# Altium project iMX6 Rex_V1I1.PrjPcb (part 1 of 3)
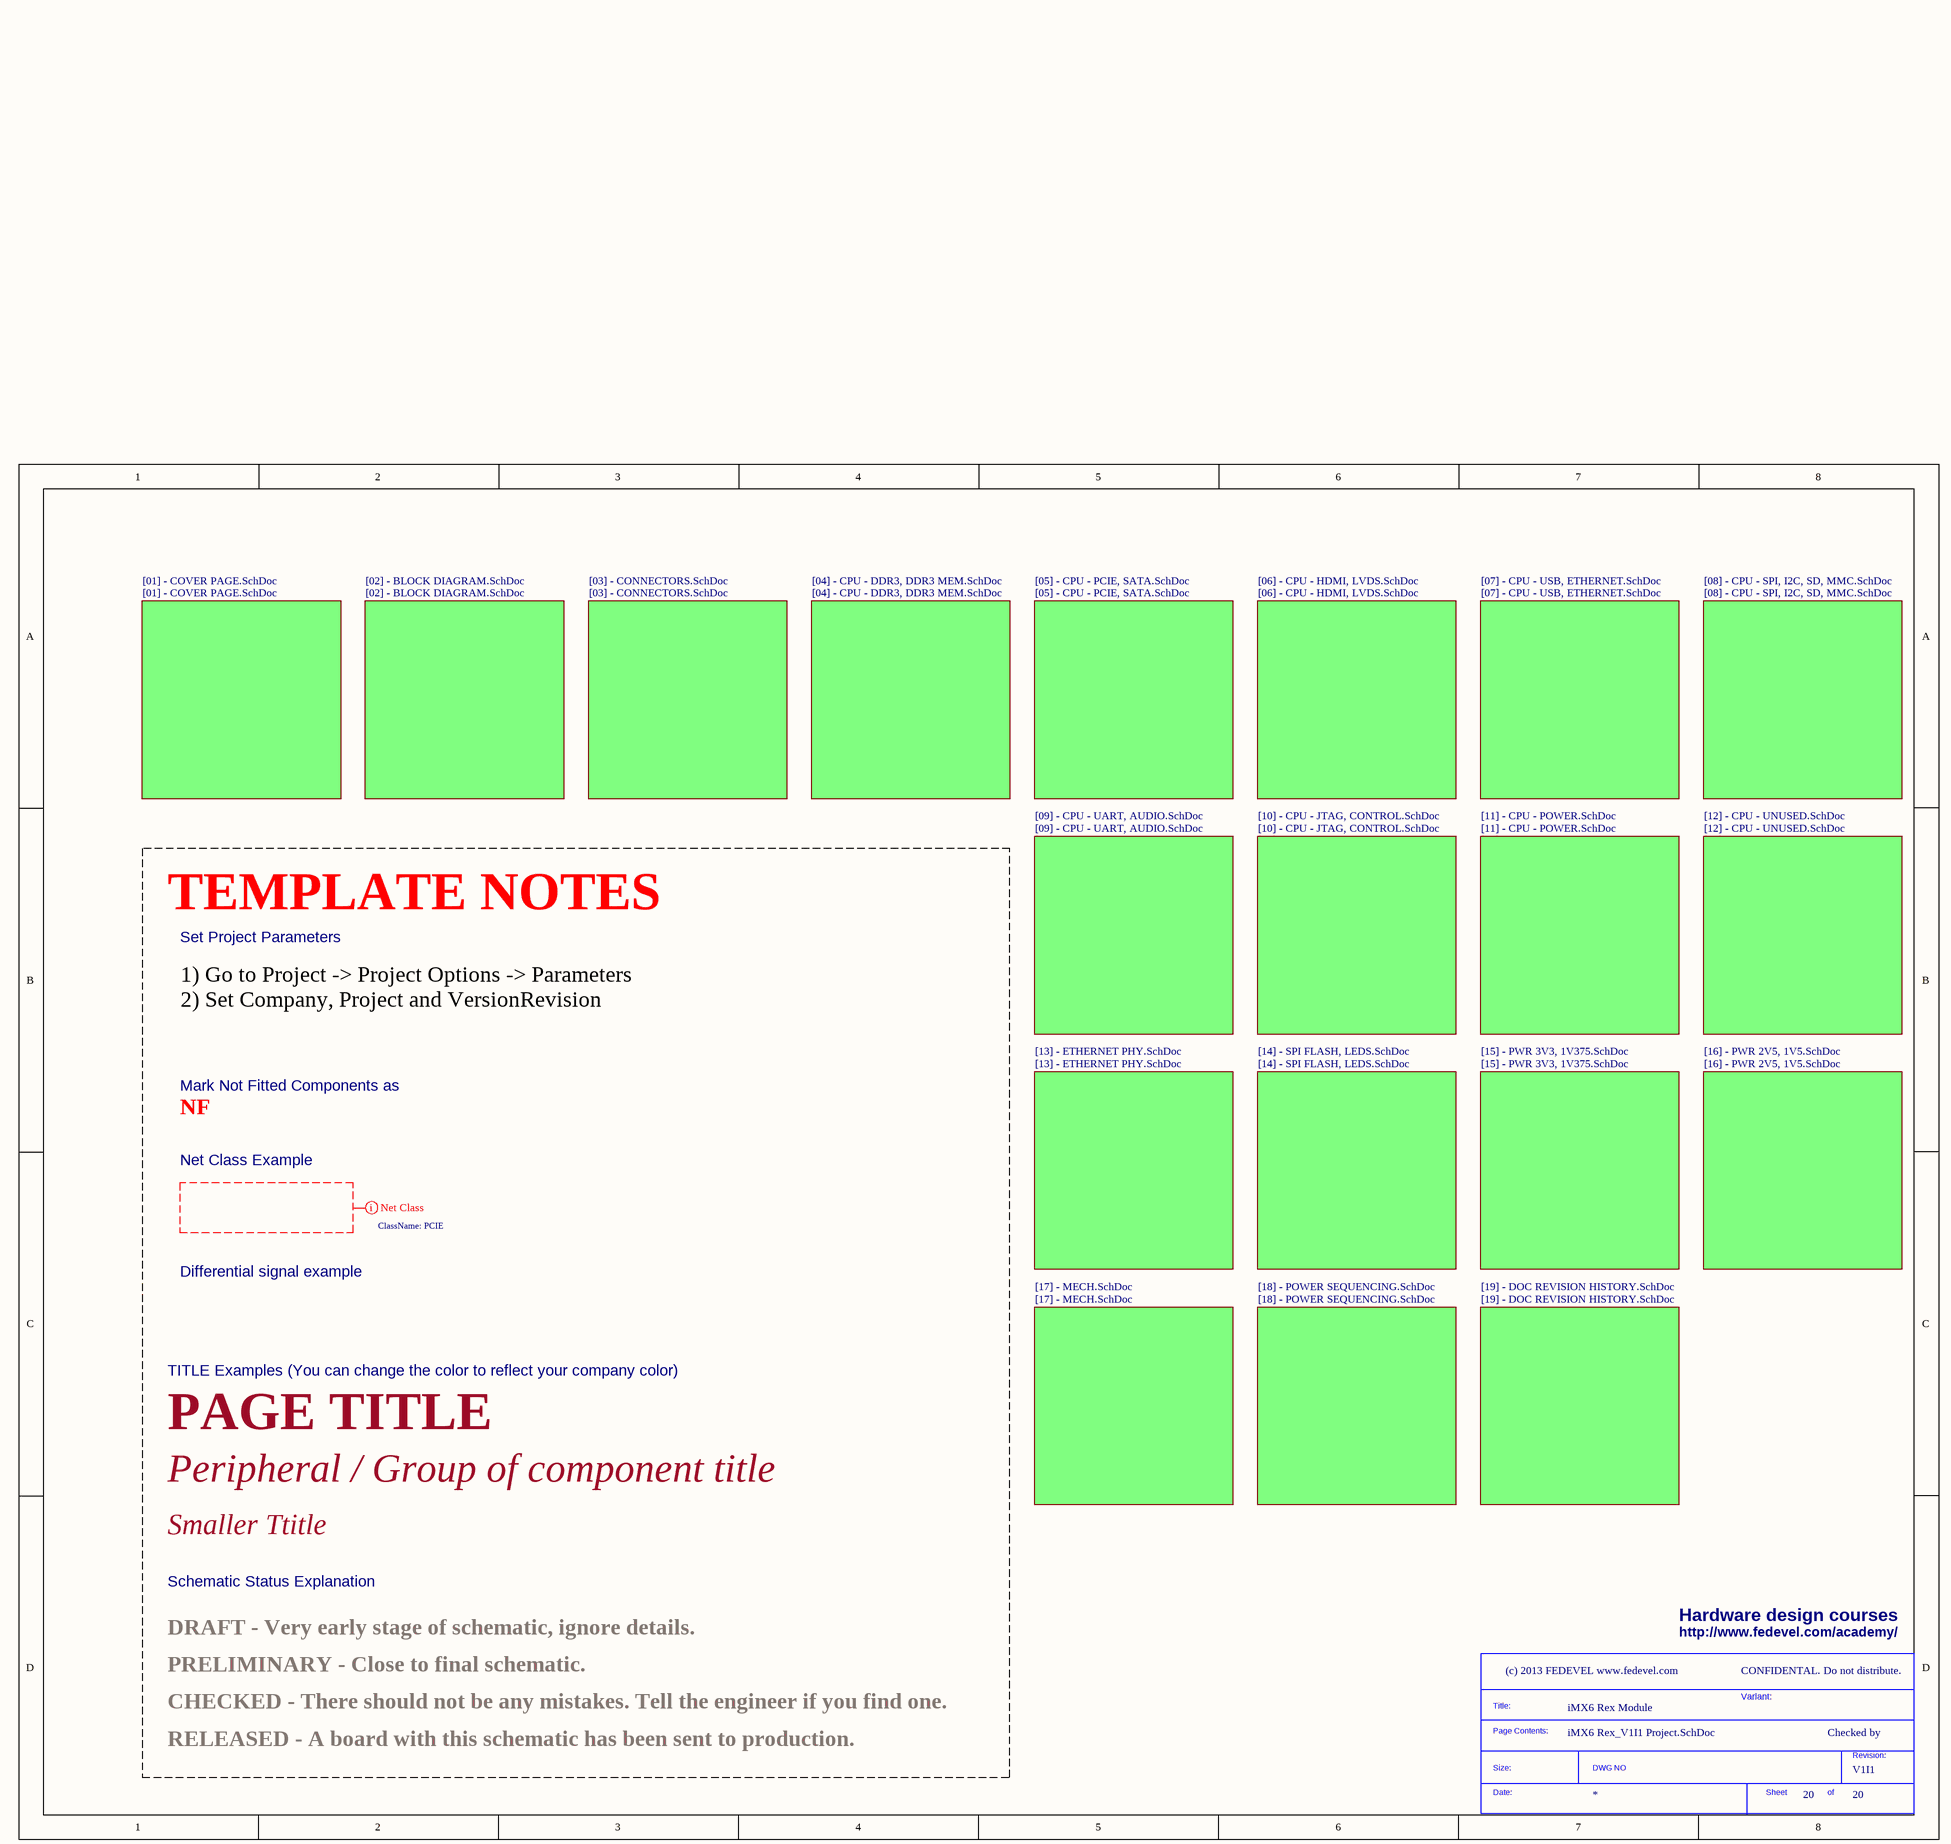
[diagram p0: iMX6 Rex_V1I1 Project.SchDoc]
ClientCompanyName: FEDEVEL Academy; ClientContactEmail: robert.feranec@fedevel.com; ClientContactName: Robert Feranec; ClientWebsite: http://www.fedevel.com/academy/; Company: (c) 2013 FEDEVEL www.fedevel.com; Project: iMX6 Rex Module; VersionRevision: V1I1
20 sheets, 495 parts. Net scope: flat (ports and power ports of the same name join across sheets).
Board file: iMX6 Rex_V1I1_PCB.PcbDoc
Sheets:
  iMX6 Rex_V1I1 Project.SchDoc
    [01] - COVER PAGE.SchDoc = [01] - COVER PAGE.SchDoc
    [02] - BLOCK DIAGRAM.SchDoc = [02] - BLOCK DIAGRAM.SchDoc
    [19] - DOC REVISION HISTORY.SchDoc = [19] - DOC REVISION HISTORY.SchDoc
    [04] - CPU - DDR3, DDR3 MEM.SchDoc = [04] - CPU - DDR3, DDR3 MEM.SchDoc
    [05] - CPU - PCIE, SATA.SchDoc = [05] - CPU - PCIE, SATA.SchDoc
    [06] - CPU - HDMI, LVDS.SchDoc = [06] - CPU - HDMI, LVDS.SchDoc
    [07] - CPU - USB, ETHERNET.SchDoc = [07] - CPU - USB, ETHERNET.SchDoc
    [09] - CPU - UART, AUDIO.SchDoc = [09] - CPU - UART, AUDIO.SchDoc
    [08] - CPU - SPI, I2C, SD, MMC.SchDoc = [08] - CPU - SPI, I2C, SD, MMC.SchDoc
    [03] - CONNECTORS.SchDoc = [03] - CONNECTORS.SchDoc
    [10] - CPU - JTAG, CONTROL.SchDoc = [10] - CPU - JTAG, CONTROL.SchDoc
    [11] - CPU - POWER.SchDoc = [11] - CPU - POWER.SchDoc
    [12] - CPU - UNUSED.SchDoc = [12] - CPU - UNUSED.SchDoc
    [13] - ETHERNET PHY.SchDoc = [13] - ETHERNET PHY.SchDoc
    [14] - SPI FLASH, LEDS.SchDoc = [14] - SPI FLASH, LEDS.SchDoc
    [15] - PWR 3V3, 1V375.SchDoc = [15] - PWR 3V3, 1V375.SchDoc
    [16] - PWR 2V5, 1V5.SchDoc = [16] - PWR 2V5, 1V5.SchDoc
    [17] - MECH.SchDoc = [17] - MECH.SchDoc
    [18] - POWER SEQUENCING.SchDoc = [18] - POWER SEQUENCING.SchDoc

## Sheet iMX6 Rex_V1I1 Project.SchDoc
size A3; CompanyName: FEDEVEL; Organization: FEDEVEL; DocumentNumber: 20; Revision: V1I1; SheetNumber: 20; SheetTotal: 20; PageSetup: Record=PageOptions|CenterHorizontal=True|CenterVertical=True|PrintScale=1.07|XCorrection=1.00|YCorrection=1.00|PrintKind=1|BorderSize=5000000|LeftOffset=0|BottomOffset=0|Orientation=2|PaperLength=1000|PaperWidth=1000|Scale=100|PaperSource=7|PrintQuality=600|MediaType=1|DitherType=10|PaperKind=A3|PrintScaleMode=1

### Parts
(Parts that share a designator on the sheet are numbered #1, #2 ... from top to bottom, then left to right.)
*#1  SDTitleBlock  (value not drawn)  (graphical)

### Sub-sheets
[01] - COVER PAGE.SchDoc = [01] - COVER PAGE.SchDoc: no entries
[02] - BLOCK DIAGRAM.SchDoc = [02] - BLOCK DIAGRAM.SchDoc: no entries
[03] - CONNECTORS.SchDoc = [03] - CONNECTORS.SchDoc: no entries
[04] - CPU - DDR3, DDR3 MEM.SchDoc = [04] - CPU - DDR3, DDR3 MEM.SchDoc: no entries
[05] - CPU - PCIE, SATA.SchDoc = [05] - CPU - PCIE, SATA.SchDoc: no entries
[06] - CPU - HDMI, LVDS.SchDoc = [06] - CPU - HDMI, LVDS.SchDoc: no entries
[07] - CPU - USB, ETHERNET.SchDoc = [07] - CPU - USB, ETHERNET.SchDoc: no entries
[08] - CPU - SPI, I2C, SD, MMC.SchDoc = [08] - CPU - SPI, I2C, SD, MMC.SchDoc: no entries
[09] - CPU - UART, AUDIO.SchDoc = [09] - CPU - UART, AUDIO.SchDoc: no entries
[10] - CPU - JTAG, CONTROL.SchDoc = [10] - CPU - JTAG, CONTROL.SchDoc: no entries
[11] - CPU - POWER.SchDoc = [11] - CPU - POWER.SchDoc: no entries
[12] - CPU - UNUSED.SchDoc = [12] - CPU - UNUSED.SchDoc: no entries
[13] - ETHERNET PHY.SchDoc = [13] - ETHERNET PHY.SchDoc: no entries
[14] - SPI FLASH, LEDS.SchDoc = [14] - SPI FLASH, LEDS.SchDoc: no entries
[15] - PWR 3V3, 1V375.SchDoc = [15] - PWR 3V3, 1V375.SchDoc: no entries
[16] - PWR 2V5, 1V5.SchDoc = [16] - PWR 2V5, 1V5.SchDoc: no entries
[17] - MECH.SchDoc = [17] - MECH.SchDoc: no entries
[18] - POWER SEQUENCING.SchDoc = [18] - POWER SEQUENCING.SchDoc: no entries
[19] - DOC REVISION HISTORY.SchDoc = [19] - DOC REVISION HISTORY.SchDoc: no entries

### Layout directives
net class PCIE: (no net found under the mark)

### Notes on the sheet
- TEMPLATE NOTES
- Set Project Parameters
- 1) Go to Project -> Project Options -> Parameters
  2) Set Company, Project and VersionRevision
- NF
- Mark Not Fitted Components as
- Net Class Example
- Differential signal example
- TITLE Examples (You can change the color to reflect your company color)
- PAGE TITLE
- Peripheral / Group of component title
- Smaller Ttitle
- Schematic Status Explanation
- Hardware design courses
- PRELIMINARY - Close to final schematic.
- DRAFT - Very early stage of schematic, ignore details.
- http://www.fedevel.com/academy/
- CONFIDENTAL. Do not distribute.
- CHECKED - There should not be any mistakes. Tell the engineer if you find one.
- Variant:
- Checked by
- RELEASED - A board with this schematic has been sent to production.

## Sheet [01] - COVER PAGE.SchDoc
size A3; DocumentNumber: 1; SheetNumber: 1; SheetTotal: 20
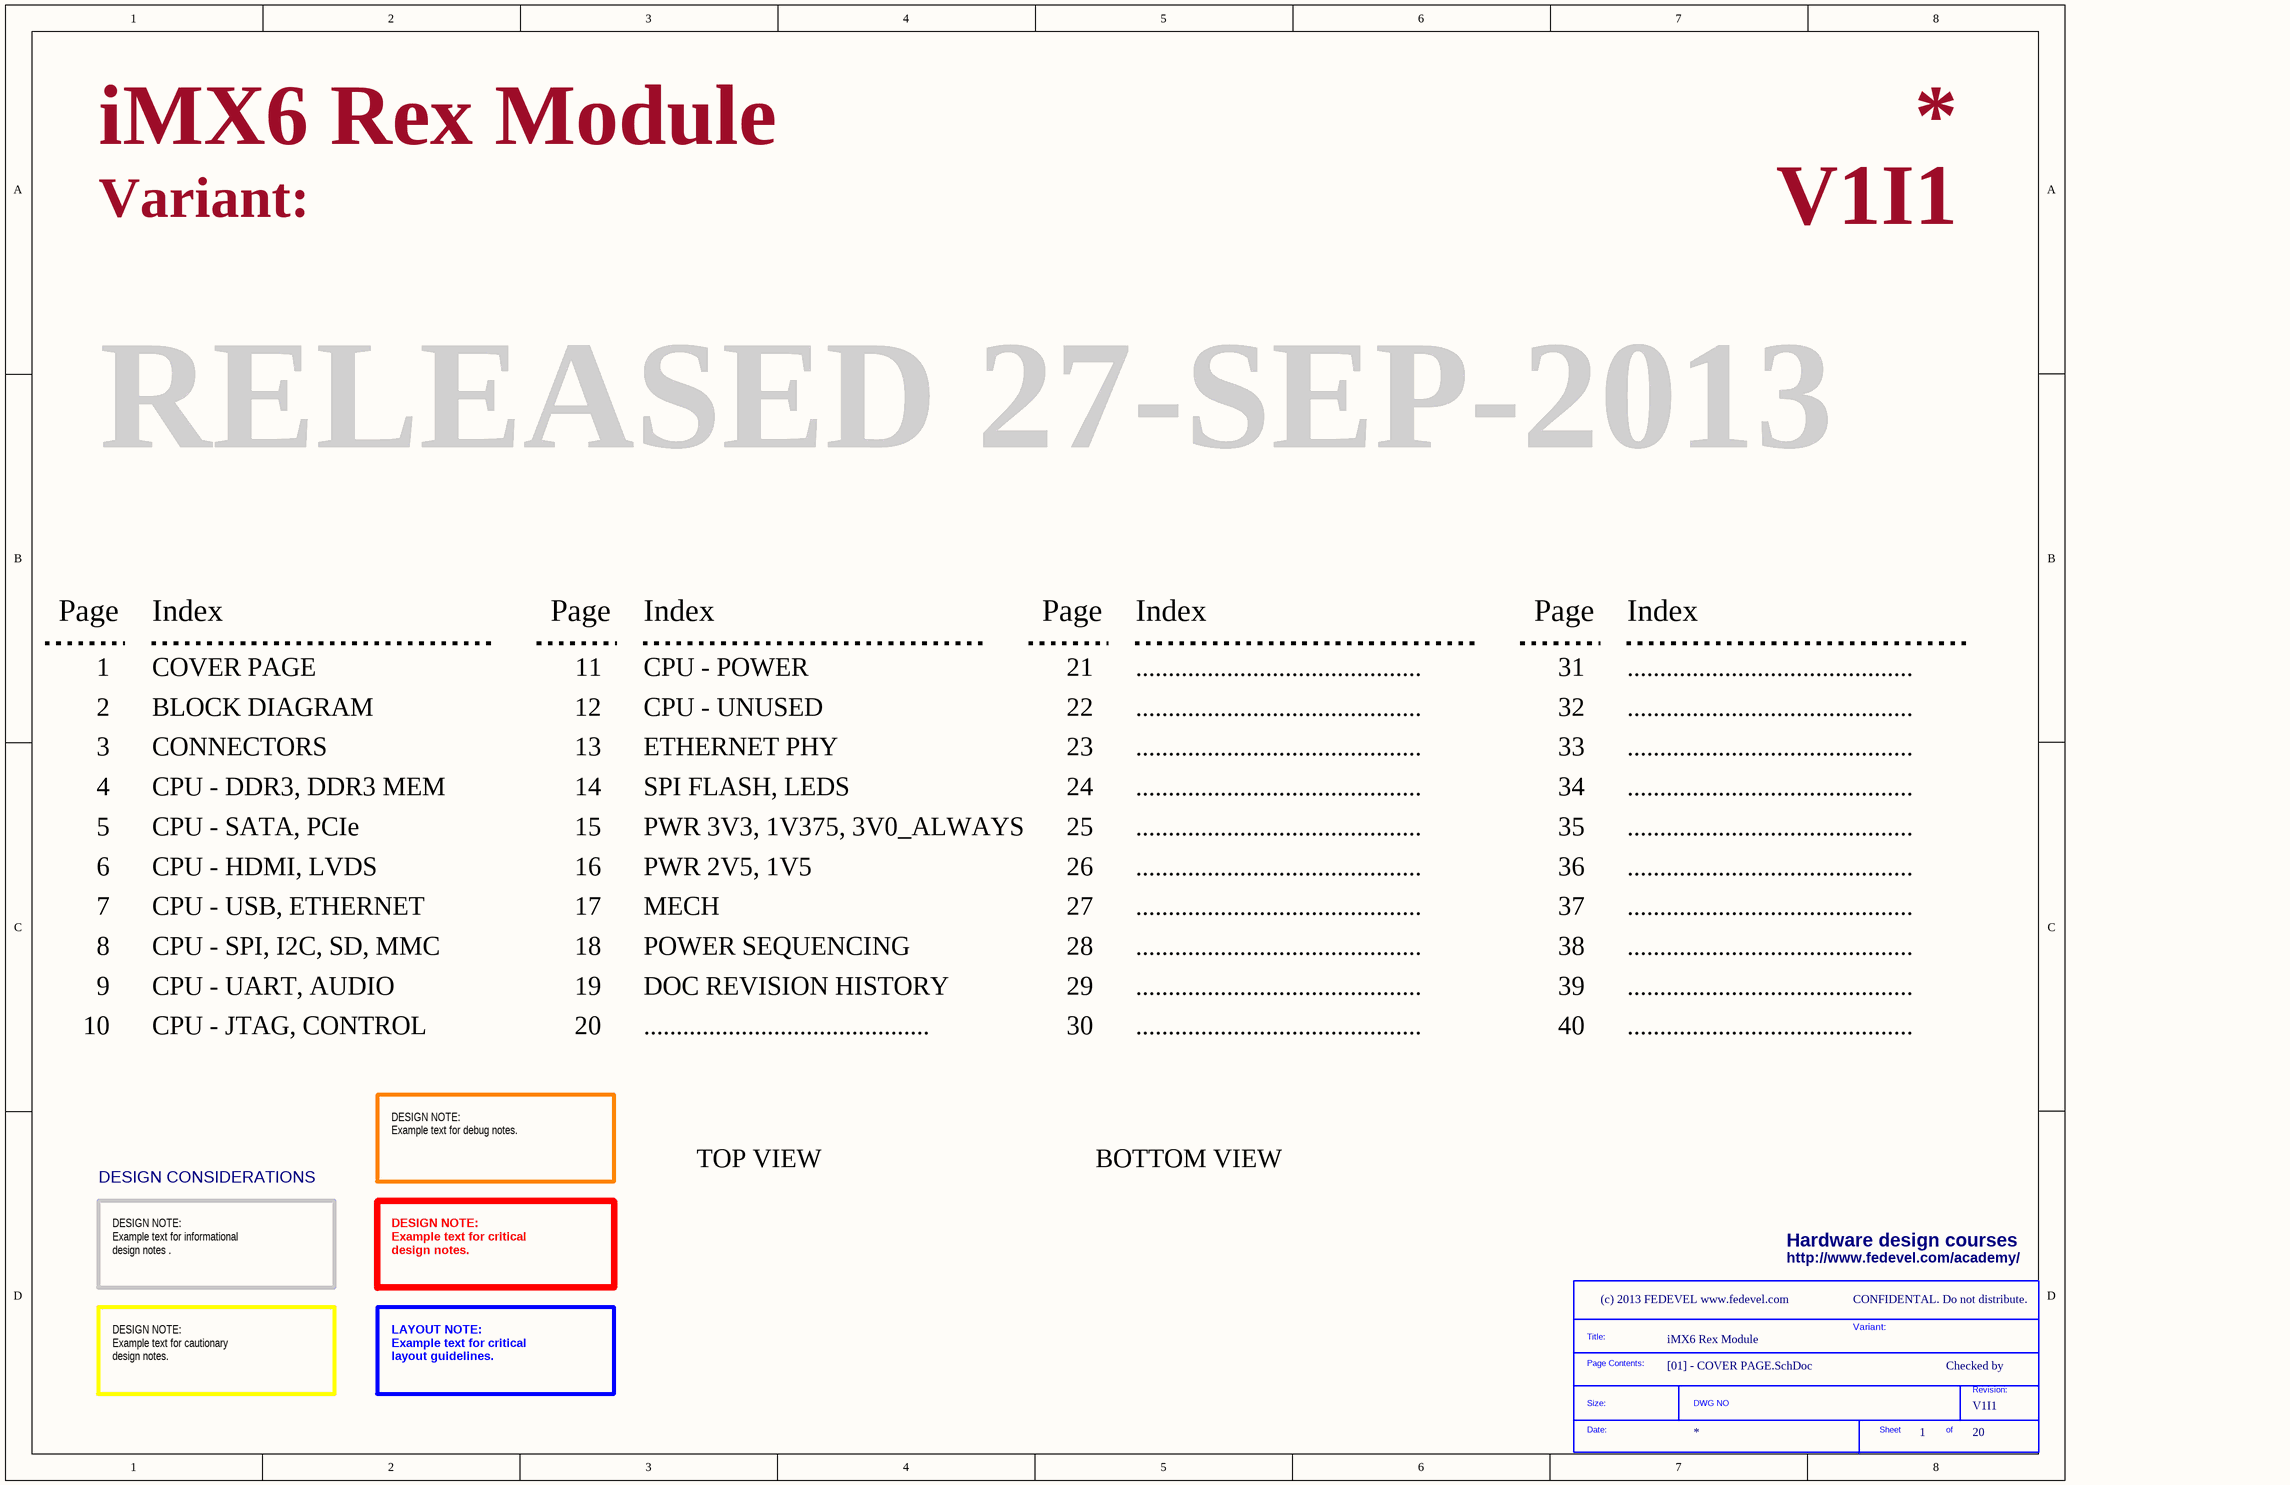
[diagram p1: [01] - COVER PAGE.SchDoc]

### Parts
(Parts that share a designator on the sheet are numbered #1, #2 ... from top to bottom, then left to right.)
*#2  SDTitleBlock  (value not drawn)  (graphical)

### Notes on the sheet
- Variant:
- RELEASED 27-SEP-2013
- Page
- Index
- 1
- COVER PAGE
- 11
- CPU - POWER
- 21
- ............................................
- 31
- 2
- 3
- BLOCK DIAGRAM
- CONNECTORS
- 12
- 13
- CPU - UNUSED
- ETHERNET PHY
- 22
- 23
- 32
- 33
- 4
- 5
- CPU - DDR3, DDR3 MEM
- CPU - SATA, PCIe
- 14
- 15
- SPI FLASH, LEDS
- PWR 3V3, 1V375, 3V0_ALWAYS
- 24
- 25
- 34
- 35
- 6
- CPU - HDMI, LVDS
- 16
- PWR 2V5, 1V5
- 26
- 36
- 7
- 8
- CPU - USB, ETHERNET
- CPU - SPI, I2C, SD, MMC
- 17
- 18
- MECH
- POWER SEQUENCING
- 27
- 28
- 37
- 38
- 9
- 10
- CPU - UART, AUDIO
- CPU - JTAG, CONTROL
- 19
- 20
- DOC REVISION HISTORY
- 29
- 30
- 39
- 40
- DESIGN NOTE:
  Example text for debug notes.
- TOP VIEW
- BOTTOM VIEW
- DESIGN CONSIDERATIONS
- Hardware design courses
- DESIGN NOTE:
  Example text for informational
  design notes .
- DESIGN NOTE:
  Example text for critical
  design notes.
- http://www.fedevel.com/academy/
- CONFIDENTAL. Do not distribute.
- Checked by
- DESIGN NOTE:
  Example text for cautionary
  design notes.
- LAYOUT NOTE:
  Example text for critical
  layout guidelines.

## Sheet [02] - BLOCK DIAGRAM.SchDoc
size A3; DocumentNumber: 2; SheetNumber: 2; SheetTotal: 20
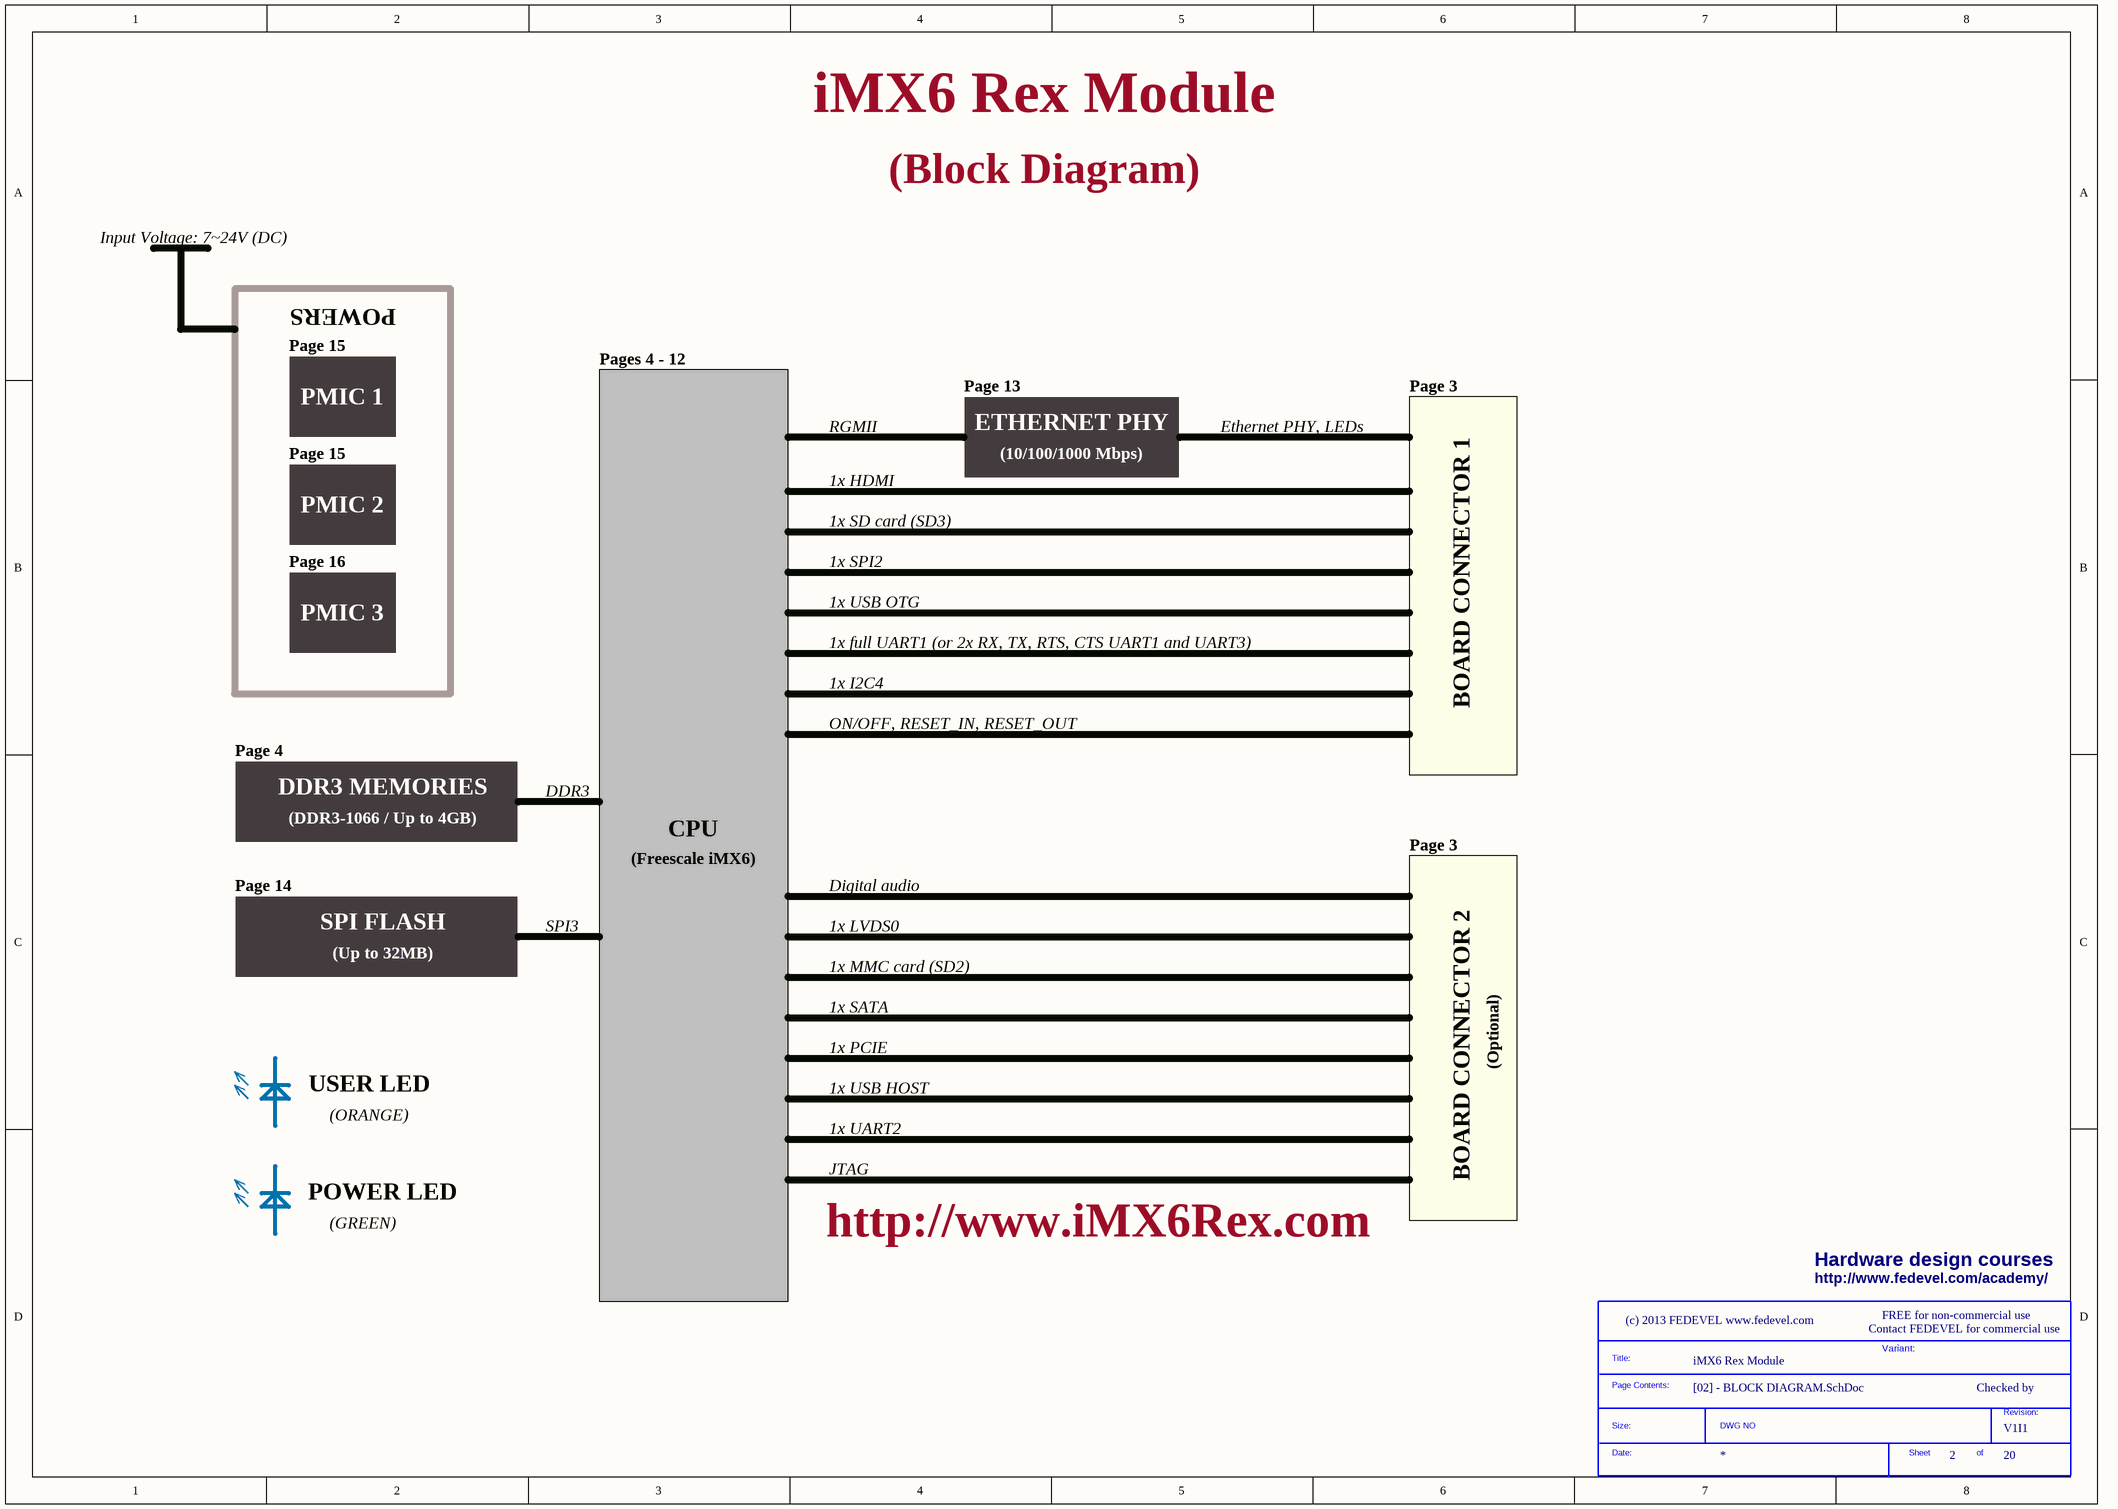
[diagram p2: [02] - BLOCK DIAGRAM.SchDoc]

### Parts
(Parts that share a designator on the sheet are numbered #1, #2 ... from top to bottom, then left to right.)
*#3  SDTitleBlock  (value not drawn)  (graphical)

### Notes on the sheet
- Input Voltage: 7|4V (DC)
- (Block Diagram)
- POWERS
- Page 15
- Pages 4 - 12
- PMIC 1
- RGMII
- Page 13
- ETHERNET PHY
- Ethernet PHY, LEDs
- Page 3
- PMIC 2
- 1x HDMI
- (10/100/1000 Mbps)
- Page 16
- 1x SD card (SD3)
- 1x SPI2
- BOARD CONNECTOR 1
- PMIC 3
- 1x USB OTG
- 1x full UART1 (or 2x RX, TX, RTS, CTS UART1 and UART3)
- 1x I2C4
- Page 4
- ON/OFF, RESET_IN, RESET_OUT
- DDR3 MEMORIES
- (DDR3-1066 / Up to 4GB)
- DDR3
- CPU
- Page 14
- (Freescale iMX6)
- Digital audio
- SPI FLASH
- (Up to 32MB)
- SPI3
- 1x LVDS0
- 1x MMC card (SD2)
- 1x SATA
- 1x PCIE
- BOARD CONNECTOR 2
- (Optional)
- (ORANGE)
- USER LED
- 1x USB HOST
- 1x UART2
- JTAG
- (GREEN)
- POWER LED
- http://www.iMX6Rex.com
- Hardware design courses
- http://www.fedevel.com/academy/
- Contact FEDEVEL for commercial use
- FREE for non-commercial use
- Variant:
- Checked by

## Sheet [19] - DOC REVISION HISTORY.SchDoc
size A3; DocumentNumber: 19; SheetNumber: 19; SheetTotal: 20
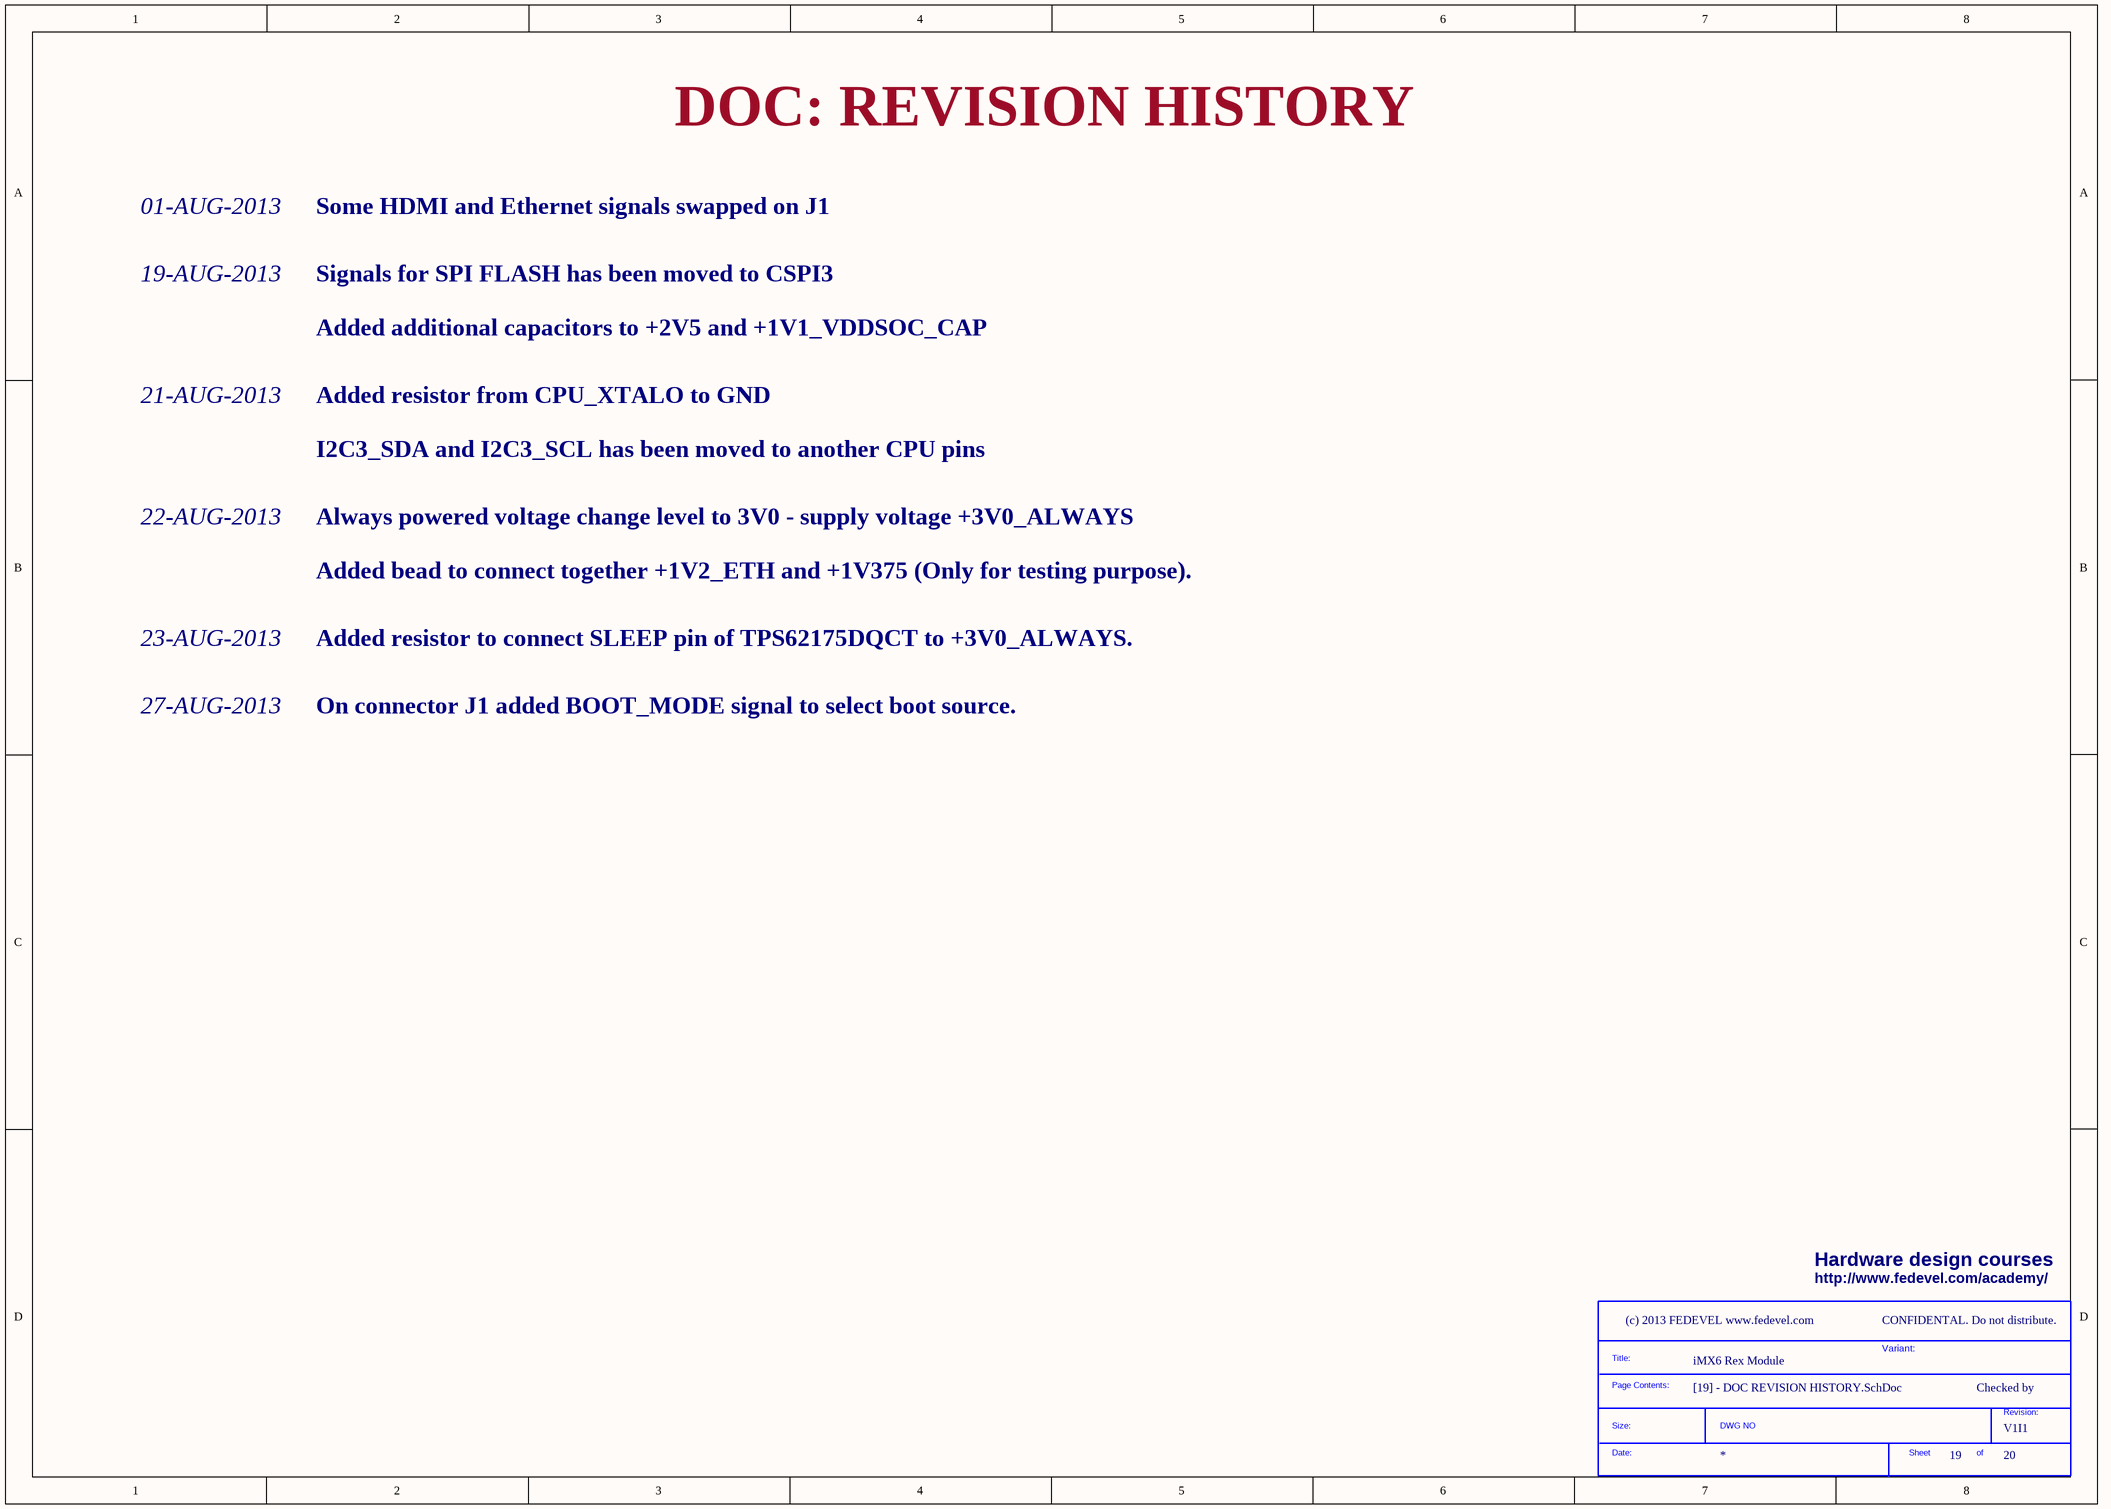
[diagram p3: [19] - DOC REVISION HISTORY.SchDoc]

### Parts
(Parts that share a designator on the sheet are numbered #1, #2 ... from top to bottom, then left to right.)
*#4  SDTitleBlock  (value not drawn)  (graphical)

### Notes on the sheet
- DOC: REVISION HISTORY
- 01-AUG-2013
- Some HDMI and Ethernet signals swapped on J1
- 19-AUG-2013
- Signals for SPI FLASH has been moved to CSPI3
- Added additional capacitors to +2V5 and +1V1_VDDSOC_CAP
- 21-AUG-2013
- Added resistor from CPU_XTALO to GND
- I2C3_SDA and I2C3_SCL has been moved to another CPU pins
- 22-AUG-2013
- Always powered voltage change level to 3V0 - supply voltage +3V0_ALWAYS
- Added bead to connect together +1V2_ETH and +1V375 (Only for testing purpose).
- 23-AUG-2013
- Added resistor to connect SLEEP pin of TPS62175DQCT to +3V0_ALWAYS.
- 27-AUG-2013
- On connector J1 added BOOT_MODE signal to select boot source.
- Hardware design courses
- http://www.fedevel.com/academy/
- CONFIDENTAL. Do not distribute.
- Variant:
- Checked by
- CLOCKS (CPU & PCIE)

## Sheet [04] - CPU - DDR3, DDR3 MEM.SchDoc
size A2; DocumentNumber: 4; SheetNumber: 4; SheetTotal: 20
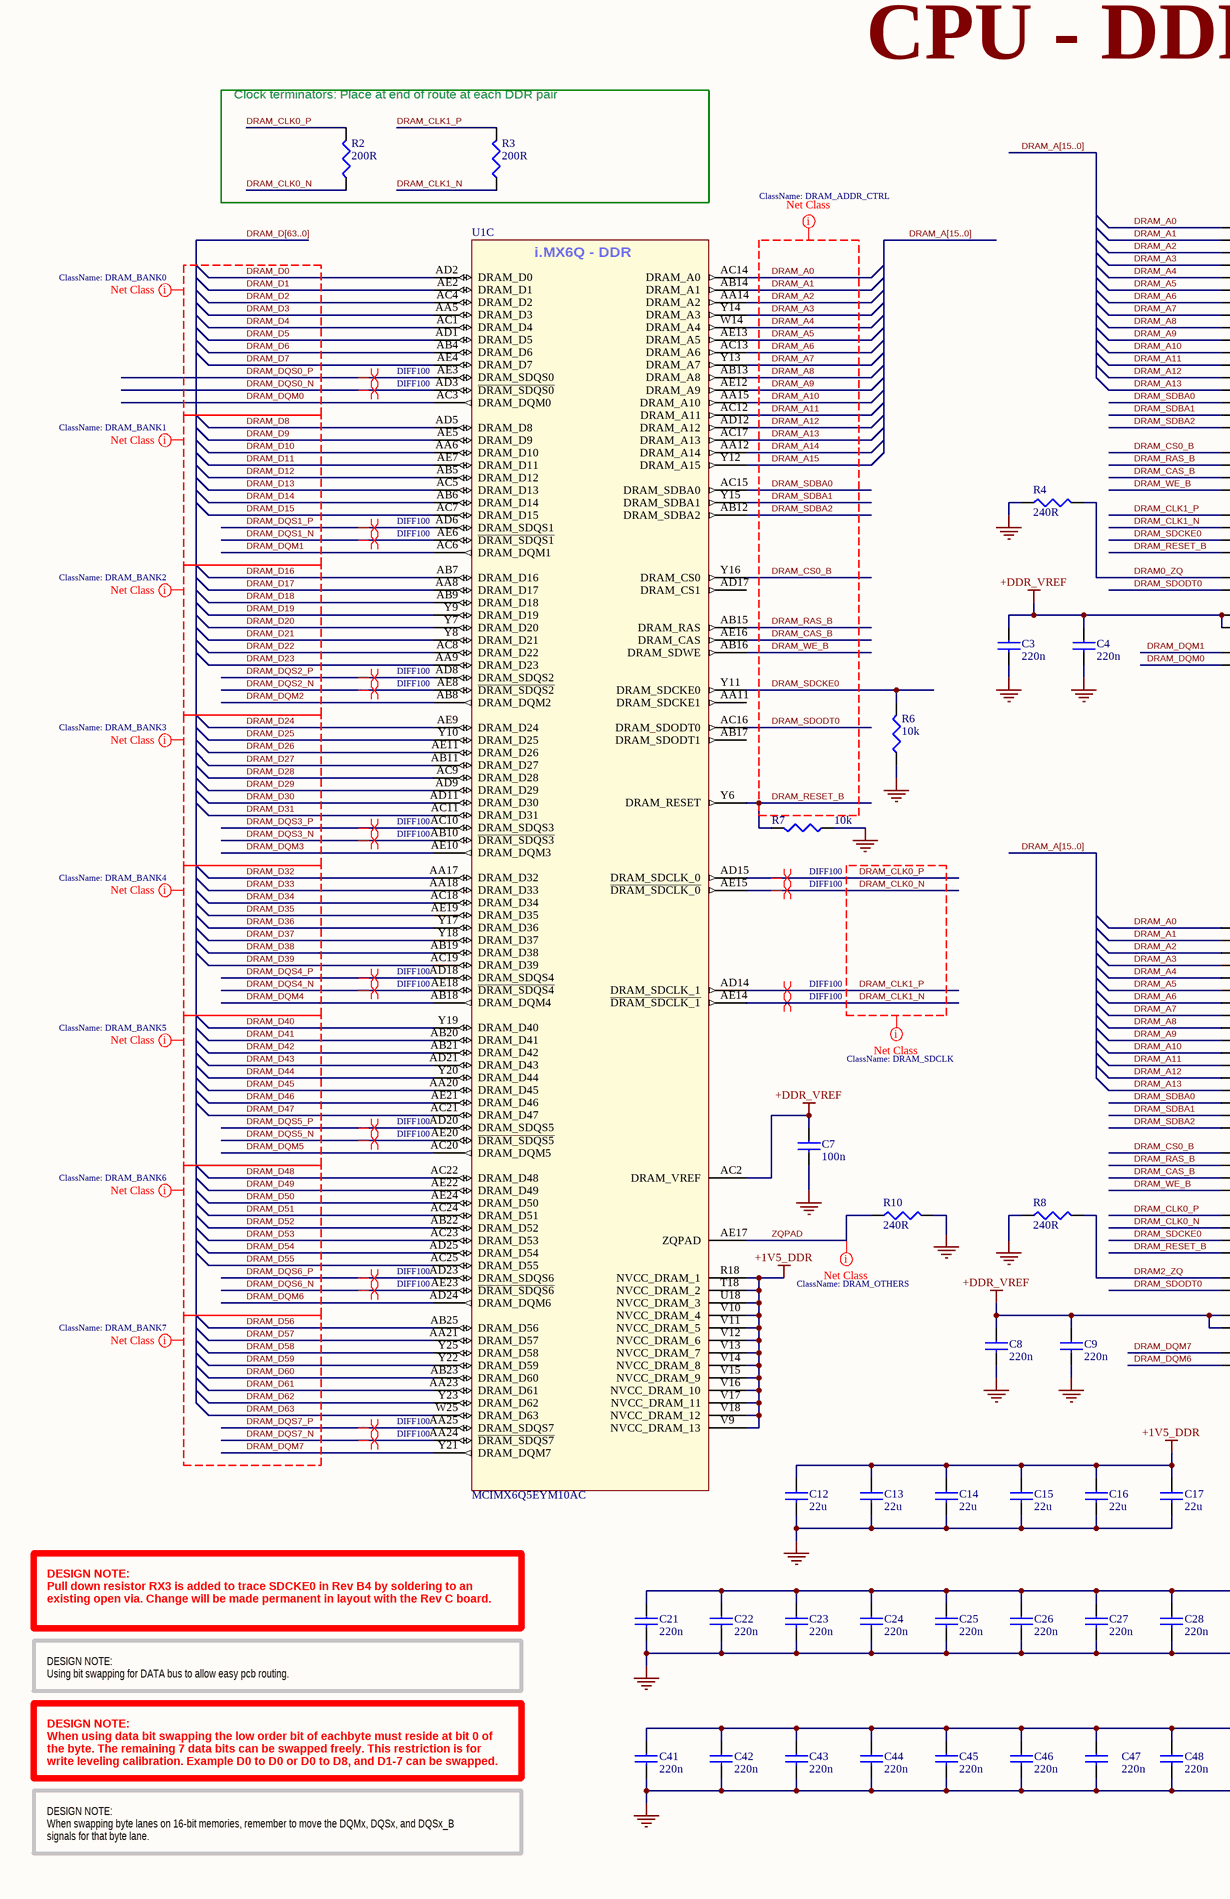
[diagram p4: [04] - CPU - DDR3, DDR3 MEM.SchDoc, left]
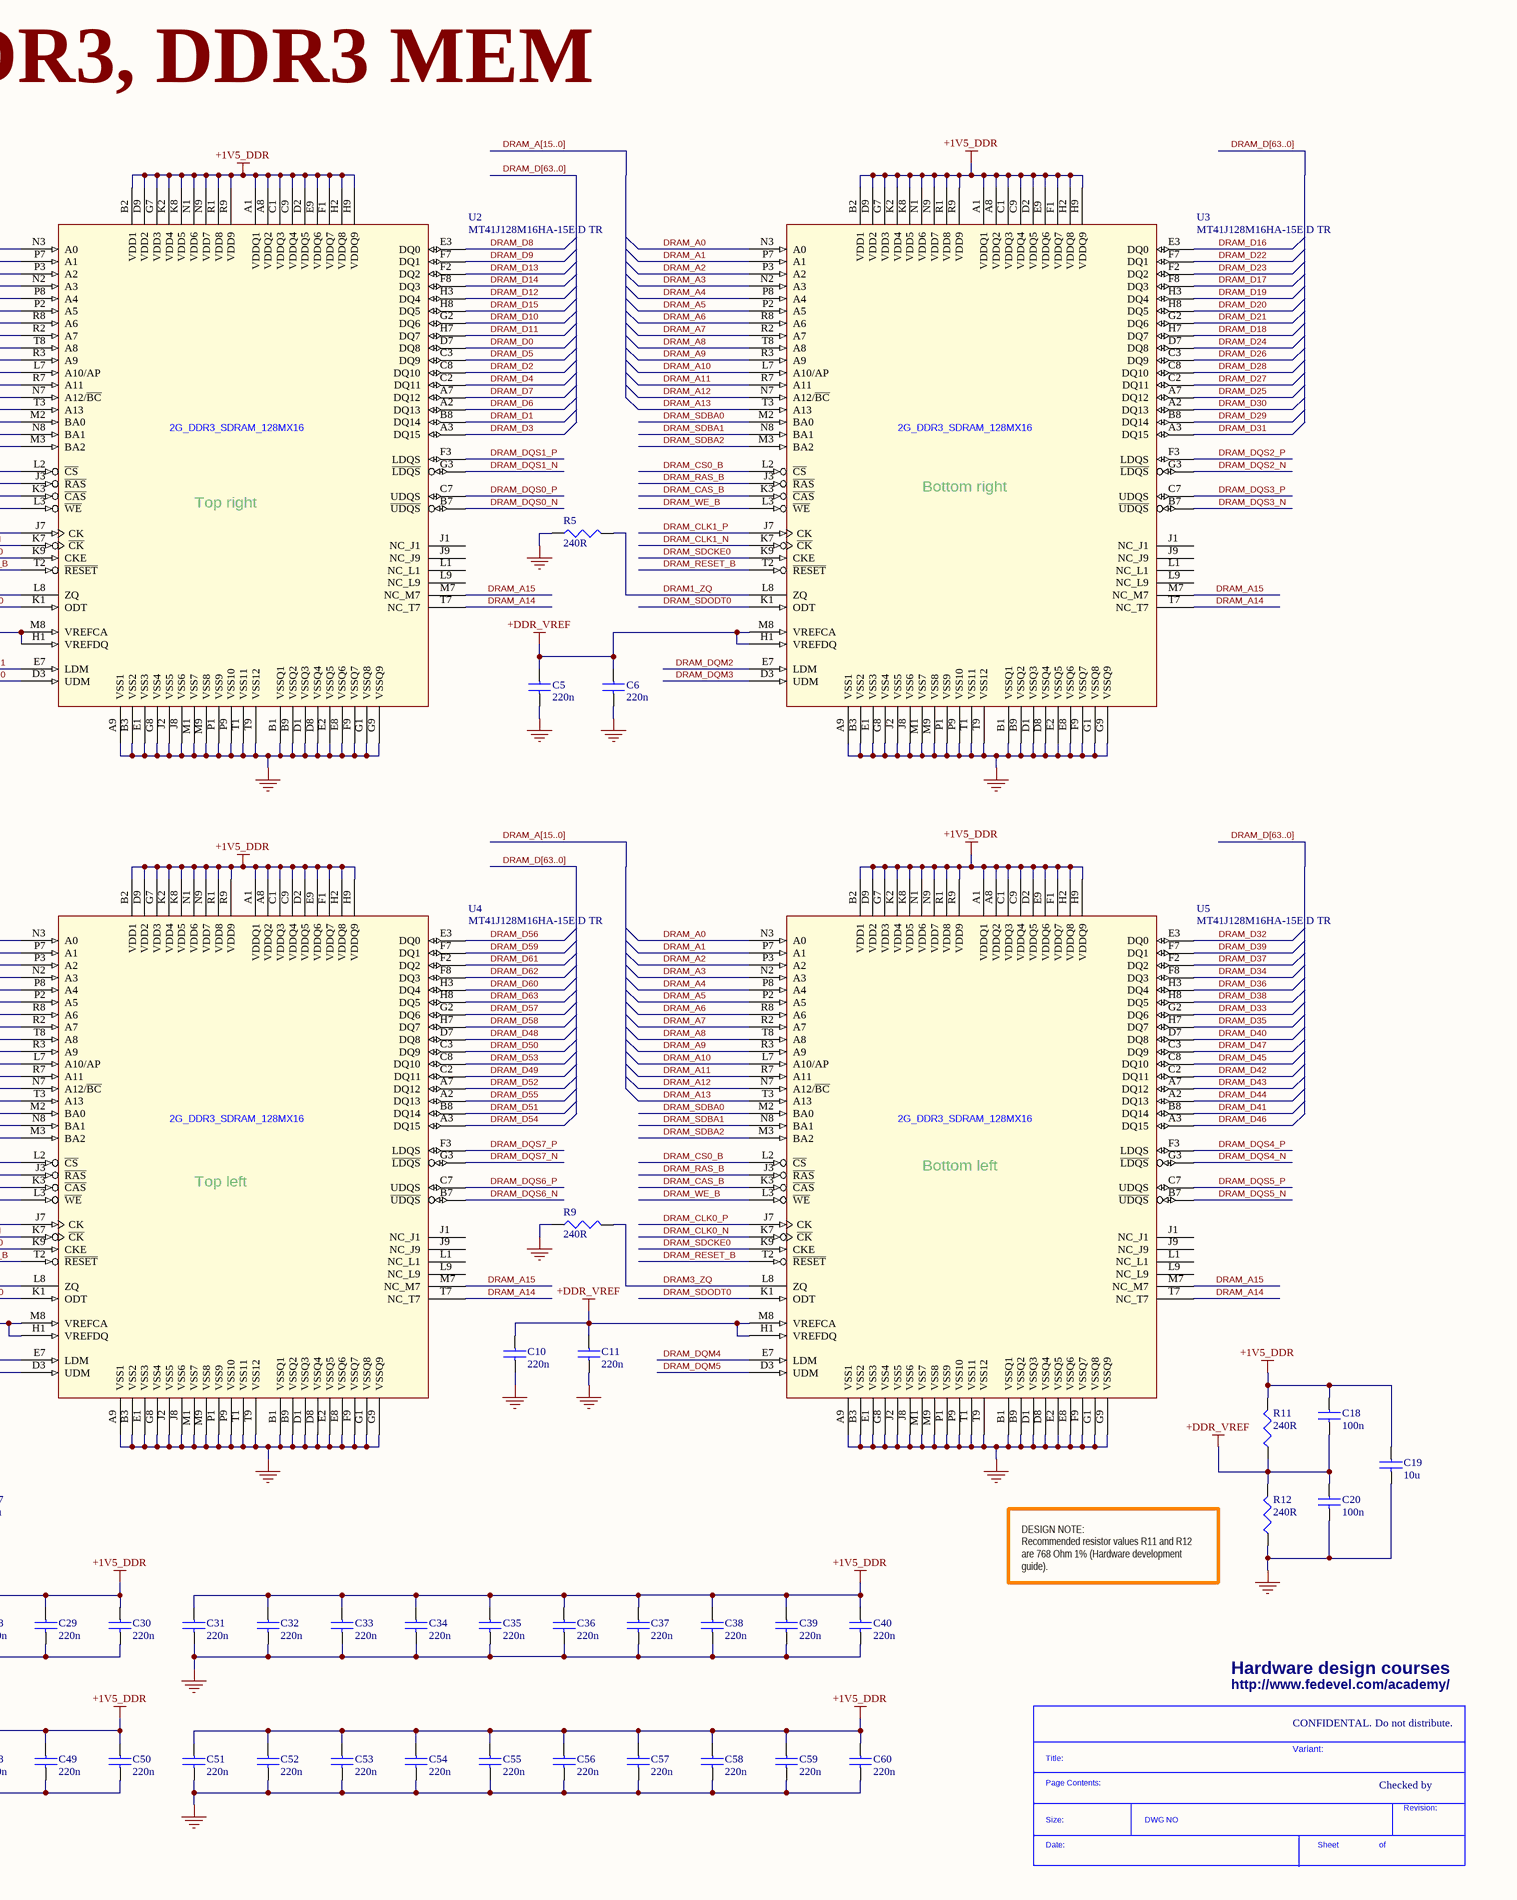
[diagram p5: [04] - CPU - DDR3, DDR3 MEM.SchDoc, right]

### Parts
(Parts that share a designator on the sheet are numbered #1, #2 ... from top to bottom, then left to right.)
*#5  SDTitleBlock  (value not drawn)  (graphical)
C3  220n  [C0402]
C4  220n  [C0402]
C5  220n  [C0402]
C6  220n  [C0402]
C7  100n  [C0402]
C8  220n  [C0402]
C9  220n  [C0402]
C10  220n  [C0402]
C11  220n  [C0402]
C12  22u  [C0603]
C13  22u  [C0603]
C14  22u  [C0603]
C15  22u  [C0603]
C16  22u  [C0603]
C17  22u  [C0603]
C18  100n  [C0402]
C19  10u  [C0603]
C20  100n  [C0402]
C21  220n  [C0402]
C22  220n  [C0402]
C23  220n  [C0402]
C24  220n  [C0402]
C25  220n  [C0402]
C26  220n  [C0402]
C27  220n  [C0402]
C28  220n  [C0402]
C29  220n  [C0402]
C30  220n  [C0402]
C31  220n  [C0402]
C32  220n  [C0402]
C33  220n  [C0402]
C34  220n  [C0402]
C35  220n  [C0402]
C36  220n  [C0402]
C37  220n  [C0402]
C38  220n  [C0402]
C39  220n  [C0402]
C40  220n  [C0402]
C41  220n  [C0402]
C42  220n  [C0402]
C43  220n  [C0402]
C44  220n  [C0402]
C45  220n  [C0402]
C46  220n  [C0402]
C47  220n  [C0402]
C48  220n  [C0402]
C49  220n  [C0402]
C50  220n  [C0402]
C51  220n  [C0402]
C52  220n  [C0402]
C53  220n  [C0402]
C54  220n  [C0402]
C55  220n  [C0402]
C56  220n  [C0402]
C57  220n  [C0402]
C58  220n  [C0402]
C59  220n  [C0402]
C60  220n  [C0402]
R2  200R  [R0402]
R3  200R  [R0402]
R4  240R  [R0402]
R5  240R  [R0402]
R6  10k  [R0402]
R7  10k  [R0402]
R8  240R  [R0402]
R9  240R  [R0402]
R10  240R  [R0402]
R11  240R  [R0402]
R12  240R  [R0402]
U1  MCIMX6Q5EYM10AC  [PBGA624]  (part C of 15)
U2  MT41J128M16HA-15E:D TR  [96_FPGA_DD3]
U3  MT41J128M16HA-15E:D TR  [96_FPGA_DD3]
U4  MT41J128M16HA-15E:D TR  [96_FPGA_DD3]
U5  MT41J128M16HA-15E:D TR  [96_FPGA_DD3]

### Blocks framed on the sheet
Clock terminators: Place at end of route at each DDR pair: R2 R3

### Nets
+1V5_DDR: C12.1 C13.1 C14.1 C15.1 C16.1 C17.1 C18.1 C19.1 C21.1 C22.1 C23.1 C24.1 C25.1 C26.1 C27.1 C28.1 C29.1 C30.1 C31.1 C32.1 C33.1 C34.1 C35.1 C36.1 C37.1 C38.1 C39.1 C40.1 C41.1 C42.1 C43.1 C44.1 C45.1 C46.1 C47.1 C48.1 C49.1 C50.1 C51.1 C52.1 C53.1 C54.1 C55.1 C56.1 C57.1 C58.1 C59.1 C60.1 R11.2 U1.R18(NVCC_DRAM_1) U1.T18(NVCC_DRAM_2) U1.U18(NVCC_DRAM_3) U1.V9(NVCC_DRAM_13) U1.V10(NVCC_DRAM_4) U1.V11(NVCC_DRAM_5) U1.V12(NVCC_DRAM_6) U1.V13(NVCC_DRAM_7) U1.V14(NVCC_DRAM_8) U1.V15(NVCC_DRAM_9) U1.V16(NVCC_DRAM_10) U1.V17(NVCC_DRAM_11) U1.V18(NVCC_DRAM_12) U2.A1(VDDQ1) U2.A8(VDDQ2) U2.B2(VDD1) U2.C1(VDDQ3) U2.C9(VDDQ4) U2.D2(VDDQ5) U2.D9(VDD2) U2.E9(VDDQ6) U2.F1(VDDQ7) U2.G7(VDD3) U2.H2(VDDQ8) U2.H9(VDDQ9) U2.K2(VDD4) U2.K8(VDD5) U2.N1(VDD6) U2.N9(VDD7) U2.R1(VDD8) U2.R9(VDD9) U3.A1(VDDQ1) U3.A8(VDDQ2) U3.B2(VDD1) U3.C1(VDDQ3) U3.C9(VDDQ4) U3.D2(VDDQ5) U3.D9(VDD2) U3.E9(VDDQ6) U3.F1(VDDQ7) U3.G7(VDD3) U3.H2(VDDQ8) U3.H9(VDDQ9) U3.K2(VDD4) U3.K8(VDD5) U3.N1(VDD6) U3.N9(VDD7) U3.R1(VDD8) U3.R9(VDD9) U4.A1(VDDQ1) U4.A8(VDDQ2) U4.B2(VDD1) U4.C1(VDDQ3) U4.C9(VDDQ4) U4.D2(VDDQ5) U4.D9(VDD2) U4.E9(VDDQ6) U4.F1(VDDQ7) U4.G7(VDD3) U4.H2(VDDQ8) U4.H9(VDDQ9) U4.K2(VDD4) U4.K8(VDD5) U4.N1(VDD6) U4.N9(VDD7) U4.R1(VDD8) U4.R9(VDD9) U5.A1(VDDQ1) U5.A8(VDDQ2) U5.B2(VDD1) U5.C1(VDDQ3) U5.C9(VDDQ4) U5.D2(VDDQ5) U5.D9(VDD2) U5.E9(VDDQ6) U5.F1(VDDQ7) U5.G7(VDD3) U5.H2(VDDQ8) U5.H9(VDDQ9) U5.K2(VDD4) U5.K8(VDD5) U5.N1(VDD6) U5.N9(VDD7) U5.R1(VDD8) U5.R9(VDD9)
+DDR_VREF: C3.1 C4.1 C5.1 C6.1 C7.1 C8.1 C9.1 C10.1 C11.1 C18.2 C20.1 R11.1 R12.2 U1.AC2(DRAM_VREF) U2.H1(VREFDQ) U2.M8(VREFCA) U3.H1(VREFDQ) U3.M8(VREFCA) U4.H1(VREFDQ) U4.M8(VREFCA) U5.H1(VREFDQ) U5.M8(VREFCA)
GND: C3.2 C4.2 C5.2 C6.2 C7.2 C8.2 C9.2 C10.2 C11.2 C12.2 C13.2 C14.2 C15.2 C16.2 C17.2 C19.2 C20.2 C21.2 C22.2 C23.2 C24.2 C25.2 C26.2 C27.2 C28.2 C29.2 C30.2 C31.2 C32.2 C33.2 C34.2 C35.2 C36.2 C37.2 C38.2 C39.2 C40.2 C41.2 C42.2 C43.2 C44.2 C45.2 C46.2 C47.2 C48.2 C49.2 C50.2 C51.2 C52.2 C53.2 C54.2 C55.2 C56.2 C57.2 C58.2 C59.2 C60.2 R4.1 R5.1 R6.1 R7.1 R8.1 R9.1 R10.2 R12.1 U2.A9(VSS1) U2.B1(VSSQ1) U2.B3(VSS2) U2.B9(VSSQ2) U2.D1(VSSQ3) U2.D8(VSSQ4) U2.E1(VSS3) U2.E2(VSSQ5) U2.E8(VSSQ6) U2.F9(VSSQ7) U2.G1(VSSQ8) U2.G8(VSS4) U2.G9(VSSQ9) U2.J2(VSS5) U2.J8(VSS6) U2.M1(VSS7) U2.M9(VSS8) U2.P1(VSS9) U2.P9(VSS10) U2.T1(VSS11) U2.T9(VSS12) U3.A9(VSS1) U3.B1(VSSQ1) U3.B3(VSS2) U3.B9(VSSQ2) U3.D1(VSSQ3) U3.D8(VSSQ4) U3.E1(VSS3) U3.E2(VSSQ5) U3.E8(VSSQ6) U3.F9(VSSQ7) U3.G1(VSSQ8) U3.G8(VSS4) U3.G9(VSSQ9) U3.J2(VSS5) U3.J8(VSS6) U3.M1(VSS7) U3.M9(VSS8) U3.P1(VSS9) U3.P9(VSS10) U3.T1(VSS11) U3.T9(VSS12) U4.A9(VSS1) U4.B1(VSSQ1) U4.B3(VSS2) U4.B9(VSSQ2) U4.D1(VSSQ3) U4.D8(VSSQ4) U4.E1(VSS3) U4.E2(VSSQ5) U4.E8(VSSQ6) U4.F9(VSSQ7) U4.G1(VSSQ8) U4.G8(VSS4) U4.G9(VSSQ9) U4.J2(VSS5) U4.J8(VSS6) U4.M1(VSS7) U4.M9(VSS8) U4.P1(VSS9) U4.P9(VSS10) U4.T1(VSS11) U4.T9(VSS12) U5.A9(VSS1) U5.B1(VSSQ1) U5.B3(VSS2) U5.B9(VSSQ2) U5.D1(VSSQ3) U5.D8(VSSQ4) U5.E1(VSS3) U5.E2(VSSQ5) U5.E8(VSSQ6) U5.F9(VSSQ7) U5.G1(VSSQ8) U5.G8(VSS4) U5.G9(VSSQ9) U5.J2(VSS5) U5.J8(VSS6) U5.M1(VSS7) U5.M9(VSS8) U5.P1(VSS9) U5.P9(VSS10) U5.T1(VSS11) U5.T9(VSS12)
DRAM0_ZQ: R4.2 U2.L8(ZQ)
DRAM1_ZQ: R5.2 U3.L8(ZQ)
DRAM2_ZQ: R8.2 U4.L8(ZQ)
DRAM3_ZQ: R9.2 U5.L8(ZQ)
DRAM_A0: U1.AC14(DRAM_A0) U2.N3(A0) U3.N3(A0) U4.N3(A0) U5.N3(A0)
DRAM_A1: U1.AB14(DRAM_A1) U2.P7(A1) U3.P7(A1) U4.P7(A1) U5.P7(A1)
DRAM_A2: U1.AA14(DRAM_A2) U2.P3(A2) U3.P3(A2) U4.P3(A2) U5.P3(A2)
DRAM_A3: U1.Y14(DRAM_A3) U2.N2(A3) U3.N2(A3) U4.N2(A3) U5.N2(A3)
DRAM_A4: U1.W14(DRAM_A4) U2.P8(A4) U3.P8(A4) U4.P8(A4) U5.P8(A4)
DRAM_A5: U1.AE13(DRAM_A5) U2.P2(A5) U3.P2(A5) U4.P2(A5) U5.P2(A5)
DRAM_A6: U1.AC13(DRAM_A6) U2.R8(A6) U3.R8(A6) U4.R8(A6) U5.R8(A6)
DRAM_A7: U1.Y13(DRAM_A7) U2.R2(A7) U3.R2(A7) U4.R2(A7) U5.R2(A7)
DRAM_A8: U1.AB13(DRAM_A8) U2.T8(A8) U3.T8(A8) U4.T8(A8) U5.T8(A8)
DRAM_A9: U1.AE12(DRAM_A9) U2.R3(A9) U3.R3(A9) U4.R3(A9) U5.R3(A9)
DRAM_A10: U1.AA15(DRAM_A10) U2.L7(A10/AP) U3.L7(A10/AP) U4.L7(A10/AP) U5.L7(A10/AP)
DRAM_A11: U1.AC12(DRAM_A11) U2.R7(A11) U3.R7(A11) U4.R7(A11) U5.R7(A11)
DRAM_A12: U1.AD12(DRAM_A12) U2.N7(A12/~{BC}) U3.N7(A12/~{BC}) U4.N7(A12/~{BC}) U5.N7(A12/~{BC})
DRAM_A13: U1.AC17(DRAM_A13) U2.T3(A13) U3.T3(A13) U4.T3(A13) U5.T3(A13)
DRAM_A14: U1.AA12(DRAM_A14) U2.T7(NC_T7) U3.T7(NC_T7) U4.T7(NC_T7) U5.T7(NC_T7)
DRAM_A15: U1.Y12(DRAM_A15) U2.M7(NC_M7) U3.M7(NC_M7) U4.M7(NC_M7) U5.M7(NC_M7)
DRAM_CAS_B: U1.AE16(DRAM_CAS) U2.K3(~{CAS}) U3.K3(~{CAS}) U4.K3(~{CAS}) U5.K3(~{CAS})
DRAM_CLK0_N: R2.1 U1.AE15(~{DRAM_SDCLK_0}) U4.K7(~{CK}) U5.K7(~{CK})
DRAM_CLK0_P: R2.2 U1.AD15(DRAM_SDCLK_0) U4.J7(CK) U5.J7(CK)
DRAM_CLK1_N: R3.1 U1.AE14(~{DRAM_SDCLK_1}) U2.K7(~{CK}) U3.K7(~{CK})
DRAM_CLK1_P: R3.2 U1.AD14(DRAM_SDCLK_1) U2.J7(CK) U3.J7(CK)
DRAM_CS0_B: U1.Y16(DRAM_CS0) U2.L2(~{CS}) U3.L2(~{CS}) U4.L2(~{CS}) U5.L2(~{CS})
DRAM_D0: U1.AD2(DRAM_D0) U2.D7(DQ8)
DRAM_D1: U1.AE2(DRAM_D1) U2.B8(DQ14)
DRAM_D2: U1.AC4(DRAM_D2) U2.C8(DQ10)
DRAM_D3: U1.AA5(DRAM_D3) U2.A3(DQ15)
DRAM_D4: U1.AC1(DRAM_D4) U2.C2(DQ11)
DRAM_D5: U1.AD1(DRAM_D5) U2.C3(DQ9)
DRAM_D6: U1.AB4(DRAM_D6) U2.A2(DQ13)
DRAM_D7: U1.AE4(DRAM_D7) U2.A7(DQ12)
DRAM_D8: U1.AD5(DRAM_D8) U2.E3(DQ0)
DRAM_D9: U1.AE5(DRAM_D9) U2.F7(DQ1)
DRAM_D10: U1.AA6(DRAM_D10) U2.G2(DQ6)
DRAM_D11: U1.AE7(DRAM_D11) U2.H7(DQ7)
DRAM_D12: U1.AB5(DRAM_D12) U2.H3(DQ4)
DRAM_D13: U1.AC5(DRAM_D13) U2.F2(DQ2)
DRAM_D14: U1.AB6(DRAM_D14) U2.F8(DQ3)
DRAM_D15: U1.AC7(DRAM_D15) U2.H8(DQ5)
DRAM_D16: U1.AB7(DRAM_D16) U3.E3(DQ0)
DRAM_D17: U1.AA8(DRAM_D17) U3.F8(DQ3)
DRAM_D18: U1.AB9(DRAM_D18) U3.H7(DQ7)
DRAM_D19: U1.Y9(DRAM_D19) U3.H3(DQ4)
DRAM_D20: U1.Y7(DRAM_D20) U3.H8(DQ5)
DRAM_D21: U1.Y8(DRAM_D21) U3.G2(DQ6)
DRAM_D22: U1.AC8(DRAM_D22) U3.F7(DQ1)
DRAM_D23: U1.AA9(DRAM_D23) U3.F2(DQ2)
DRAM_D24: U1.AE9(DRAM_D24) U3.D7(DQ8)
DRAM_D25: U1.Y10(DRAM_D25) U3.A7(DQ12)
DRAM_D26: U1.AE11(DRAM_D26) U3.C3(DQ9)
DRAM_D27: U1.AB11(DRAM_D27) U3.C2(DQ11)
DRAM_D28: U1.AC9(DRAM_D28) U3.C8(DQ10)
DRAM_D29: U1.AD9(DRAM_D29) U3.B8(DQ14)
DRAM_D30: U1.AD11(DRAM_D30) U3.A2(DQ13)
DRAM_D31: U1.AC11(DRAM_D31) U3.A3(DQ15)
DRAM_D32: U1.AA17(DRAM_D32) U5.E3(DQ0)
DRAM_D33: U1.AA18(DRAM_D33) U5.G2(DQ6)
DRAM_D34: U1.AC18(DRAM_D34) U5.F8(DQ3)
DRAM_D35: U1.AE19(DRAM_D35) U5.H7(DQ7)
DRAM_D36: U1.Y17(DRAM_D36) U5.H3(DQ4)
DRAM_D37: U1.Y18(DRAM_D37) U5.F2(DQ2)
DRAM_D38: U1.AB19(DRAM_D38) U5.H8(DQ5)
DRAM_D39: U1.AC19(DRAM_D39) U5.F7(DQ1)
DRAM_D40: U1.Y19(DRAM_D40) U5.D7(DQ8)
DRAM_D41: U1.AB20(DRAM_D41) U5.B8(DQ14)
DRAM_D42: U1.AB21(DRAM_D42) U5.C2(DQ11)
DRAM_D43: U1.AD21(DRAM_D43) U5.A7(DQ12)
DRAM_D44: U1.Y20(DRAM_D44) U5.A2(DQ13)
DRAM_D45: U1.AA20(DRAM_D45) U5.C8(DQ10)
DRAM_D46: U1.AE21(DRAM_D46) U5.A3(DQ15)
DRAM_D47: U1.AC21(DRAM_D47) U5.C3(DQ9)
DRAM_D48: U1.AC22(DRAM_D48) U4.D7(DQ8)
DRAM_D49: U1.AE22(DRAM_D49) U4.C2(DQ11)
DRAM_D50: U1.AE24(DRAM_D50) U4.C3(DQ9)
DRAM_D51: U1.AC24(DRAM_D51) U4.B8(DQ14)
DRAM_D52: U1.AB22(DRAM_D52) U4.A7(DQ12)
DRAM_D53: U1.AC23(DRAM_D53) U4.C8(DQ10)
DRAM_D54: U1.AD25(DRAM_D54) U4.A3(DQ15)
DRAM_D55: U1.AC25(DRAM_D55) U4.A2(DQ13)
DRAM_D56: U1.AB25(DRAM_D56) U4.E3(DQ0)
DRAM_D57: U1.AA21(DRAM_D57) U4.G2(DQ6)
DRAM_D58: U1.Y25(DRAM_D58) U4.H7(DQ7)
DRAM_D59: U1.Y22(DRAM_D59) U4.F7(DQ1)
DRAM_D60: U1.AB23(DRAM_D60) U4.H3(DQ4)
DRAM_D61: U1.AA23(DRAM_D61) U4.F2(DQ2)
DRAM_D62: U1.Y23(DRAM_D62) U4.F8(DQ3)
DRAM_D63: U1.W25(DRAM_D63) U4.H8(DQ5)
DRAM_DQM0: U1.AC3(DRAM_DQM0) U2.D3(UDM)
DRAM_DQM1: U1.AC6(DRAM_DQM1) U2.E7(LDM)
DRAM_DQM2: U1.AB8(DRAM_DQM2) U3.E7(LDM)
DRAM_DQM3: U1.AE10(DRAM_DQM3) U3.D3(UDM)
DRAM_DQM4: U1.AB18(DRAM_DQM4) U5.E7(LDM)
DRAM_DQM5: U1.AC20(DRAM_DQM5) U5.D3(UDM)
DRAM_DQM6: U1.AD24(DRAM_DQM6) U4.D3(UDM)
DRAM_DQM7: U1.Y21(DRAM_DQM7) U4.E7(LDM)
DRAM_DQS0_N: U1.AD3(~{DRAM_SDQS0}) U2.B7(~{UDQS})
DRAM_DQS0_P: U1.AE3(DRAM_SDQS0) U2.C7(UDQS)
DRAM_DQS1_N: U1.AE6(~{DRAM_SDQS1}) U2.G3(~{LDQS})
DRAM_DQS1_P: U1.AD6(DRAM_SDQS1) U2.F3(LDQS)
DRAM_DQS2_N: U1.AE8(~{DRAM_SDQS2}) U3.G3(~{LDQS})
DRAM_DQS2_P: U1.AD8(DRAM_SDQS2) U3.F3(LDQS)
DRAM_DQS3_N: U1.AB10(~{DRAM_SDQS3}) U3.B7(~{UDQS})
DRAM_DQS3_P: U1.AC10(DRAM_SDQS3) U3.C7(UDQS)
DRAM_DQS4_N: U1.AE18(~{DRAM_SDQS4}) U5.G3(~{LDQS})
DRAM_DQS4_P: U1.AD18(DRAM_SDQS4) U5.F3(LDQS)
DRAM_DQS5_N: U1.AE20(~{DRAM_SDQS5}) U5.B7(~{UDQS})
DRAM_DQS5_P: U1.AD20(DRAM_SDQS5) U5.C7(UDQS)
DRAM_DQS6_N: U1.AE23(~{DRAM_SDQS6}) U4.B7(~{UDQS})
DRAM_DQS6_P: U1.AD23(DRAM_SDQS6) U4.C7(UDQS)
DRAM_DQS7_N: U1.AA24(~{DRAM_SDQS7}) U4.G3(~{LDQS})
DRAM_DQS7_P: U1.AA25(DRAM_SDQS7) U4.F3(LDQS)
DRAM_RAS_B: U1.AB15(DRAM_RAS) U2.J3(~{RAS}) U3.J3(~{RAS}) U4.J3(~{RAS}) U5.J3(~{RAS})
DRAM_RESET_B: R7.2 U1.Y6(DRAM_RESET) U2.T2(~{RESET}) U3.T2(~{RESET}) U4.T2(~{RESET}) U5.T2(~{RESET})
DRAM_SDBA0: U1.AC15(DRAM_SDBA0) U2.M2(BA0) U3.M2(BA0) U4.M2(BA0) U5.M2(BA0)
DRAM_SDBA1: U1.Y15(DRAM_SDBA1) U2.N8(BA1) U3.N8(BA1) U4.N8(BA1) U5.N8(BA1)
DRAM_SDBA2: U1.AB12(DRAM_SDBA2) U2.M3(BA2) U3.M3(BA2) U4.M3(BA2) U5.M3(BA2)
DRAM_SDCKE0: R6.2 U1.Y11(DRAM_SDCKE0) U2.K9(CKE) U3.K9(CKE) U4.K9(CKE) U5.K9(CKE)
DRAM_SDODT0: U1.AC16(DRAM_SDODT0) U2.K1(ODT) U3.K1(ODT) U4.K1(ODT) U5.K1(ODT)
DRAM_WE_B: U1.AB16(DRAM_SDWE) U2.L3(~{WE}) U3.L3(~{WE}) U4.L3(~{WE}) U5.L3(~{WE})
ZQPAD: R10.1 U1.AE17(ZQPAD)

Not connected (* = marked no-connect by the designer): U1 AA11(DRAM_SDCKE1) AB17(DRAM_SDODT1) AD17(DRAM_CS1); U2 J1(NC_J1) J9(NC_J9) L1(NC_L1) L9(NC_L9); U3 J1(NC_J1) J9(NC_J9) L1(NC_L1) L9(NC_L9); U4 J1(NC_J1) J9(NC_J9) L1(NC_L1) L9(NC_L9); U5 J1(NC_J1) J9(NC_J9) L1(NC_L1) L9(NC_L9)

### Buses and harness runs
bus DRAM_A[15..0]
bus DRAM_D[63..0]

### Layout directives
net class DRAM_BANK0: DRAM_D0, DRAM_D1, DRAM_D2, DRAM_D3, DRAM_D4, DRAM_D5, DRAM_D6, DRAM_D7, DRAM_DQM0, DRAM_DQS0_N, DRAM_DQS0_P
net class DRAM_BANK1: DRAM_D8, DRAM_D9, DRAM_D10, DRAM_D11, DRAM_D12, DRAM_D13, DRAM_D14, DRAM_D15, DRAM_DQM1, DRAM_DQS1_N, DRAM_DQS1_P
net class DRAM_BANK2: DRAM_D16, DRAM_D17, DRAM_D18, DRAM_D19, DRAM_D20, DRAM_D21, DRAM_D22, DRAM_D23, DRAM_DQM2, DRAM_DQS2_N, DRAM_DQS2_P
net class DRAM_BANK3: DRAM_D24, DRAM_D25, DRAM_D26, DRAM_D27, DRAM_D28, DRAM_D29, DRAM_D30, DRAM_D31, DRAM_DQM3, DRAM_DQS3_N, DRAM_DQS3_P
net class DRAM_BANK4: DRAM_D32, DRAM_D33, DRAM_D34, DRAM_D35, DRAM_D36, DRAM_D37, DRAM_D38, DRAM_D39, DRAM_DQM4, DRAM_DQS4_N, DRAM_DQS4_P
net class DRAM_BANK5: DRAM_D40, DRAM_D41, DRAM_D42, DRAM_D43, DRAM_D44, DRAM_D45, DRAM_D46, DRAM_D47, DRAM_DQM5, DRAM_DQS5_N, DRAM_DQS5_P
net class DRAM_BANK6: DRAM_D48, DRAM_D49, DRAM_D50, DRAM_D51, DRAM_D52, DRAM_D53, DRAM_D54, DRAM_D55, DRAM_DQM6, DRAM_DQS6_N, DRAM_DQS6_P
net class DRAM_BANK7: DRAM_D56, DRAM_D57, DRAM_D58, DRAM_D59, DRAM_D60, DRAM_D61, DRAM_D62, DRAM_D63, DRAM_DQM7, DRAM_DQS7_N, DRAM_DQS7_P
differential pair; net class DIFF100: DRAM_CLK0_N, DRAM_CLK0_P, DRAM_CLK1_N, DRAM_CLK1_P, DRAM_DQS0_N, DRAM_DQS0_P, DRAM_DQS1_N, DRAM_DQS1_P, DRAM_DQS2_N, DRAM_DQS2_P, DRAM_DQS3_N, DRAM_DQS3_P, DRAM_DQS4_N, DRAM_DQS4_P, DRAM_DQS5_N, DRAM_DQS5_P, DRAM_DQS6_N, DRAM_DQS6_P, DRAM_DQS7_N, DRAM_DQS7_P
net class DRAM_ADDR_CTRL: DRAM_A0, DRAM_A1, DRAM_A2, DRAM_A3, DRAM_A4, DRAM_A5, DRAM_A6, DRAM_A7, DRAM_A8, DRAM_A9, DRAM_A10, DRAM_A11, DRAM_A12, DRAM_A13, DRAM_A14, DRAM_A15, DRAM_CAS_B, DRAM_CS0_B, DRAM_RAS_B, DRAM_RESET_B, DRAM_SDBA0, DRAM_SDBA1, DRAM_SDBA2, DRAM_SDCKE0, DRAM_SDODT0, DRAM_WE_B
net class DRAM_SDCLK: DRAM_CLK0_N, DRAM_CLK0_P, DRAM_CLK1_N, DRAM_CLK1_P
net class DRAM_OTHERS: ZQPAD

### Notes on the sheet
- CPU - DDR3, DDR3 MEM
- (near U2) Top right
- (near U3) Bottom right
- (near U4) Top left
- (near U5) Bottom left
- DESIGN NOTE:
  Pull down resistor RX3 is added to trace SDCKE0 in Rev B4 by soldering to an existing open via. Change will be made permanent in layout with the Rev C board.
- DESIGN NOTE:
  Recommended resistor values R11 and R12 are 768 Ohm 1% (Hardware development guide).
- Hardware design courses
- DESIGN NOTE:
  Using bit swapping for DATA bus to allow easy pcb routing.
- http://www.fedevel.com/academy/
- CONFIDENTAL. Do not distribute.
- DESIGN NOTE:
  When using data bit swapping the low order bit of eachbyte must reside at bit 0 of the byte. The remaining 7 data bits can be swapped freely. This restriction is for write leveling calibration. Example D0 to D0 or D0 to D8, and D1-7 can be swapped.
- Variant:
- Checked by
- DESIGN NOTE:
  When swapping byte lanes on 16-bit memories, remember to move the DQMx, DQSx, and DQSx_B signals for that byte lane.

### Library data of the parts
C3-C6 C8-C11 C21-C60 = C1005X5R1E224M: CAP CER .22UF 25V X5R 20% 0402; Manufacturer: TDK Corporation; Capacitance: 0.22µF; Value: 220nF; .Checked PCB: used; Description: CAP CER 0.22UF 25V 20% X5R 0402
C7 C18 C20 = C1005X5R1H104K: CAP CER .10UF 50V X5R 10% 0402; Manufacturer: TDK Corporation; Capacitance: 0.1µF; Value: 100nF; .Checked PCB: used; Description: CAP CER 0.1UF 50V 10% X5R 0402
C12-C17 = GRM188R60G226MEA0L: CAP CER 22UF 4V 20% X5R 0603; Manufacturer: Murata Electronics North America; Capacitance: 22µF; .Checked PCB: RF, used by MM; .Checked SCH: MM, checked by RF; .Creator: MM
C19 = C1608X5R0J106M: CAP CER 10UF 6.3V X5R 20% 0603; Manufacturer: TDK Corporation; Capacitance: 10µF; Value: 10µF; .Checked PCB: used; Description: CAP CER 10UF 6.3V 20% X5R 0603
R2 R3 = CRCW0402200RFKED: RES 200 OHM 1/16W 1% 0402 SMD; Manufacturer: Vishay Dale; Resistance (Ohms): 200; Power (Watts): 0.063W, 1/16W; Temperature Coefficient: ±100ppm/°C; .Checked PCB: RF, used by MM; .Checked SCH: MM, checked by RF; .Creator: MM
R4 R5 R8-R12 = RMCF0402FT240R: RES TF 240 OHM 1% 0.0625W 0402; Manufacturer: Stackpole Electronics Inc; Resistance (Ohms): 240; Power (Watts): 0.063W, 1/16W; .Checked PCB: used; Temperature Coefficient: ±100ppm/°C
R6 R7 = RC0402FR-0710KL: RES 10.0K OHM 1/16W 1% 0402 SMD; Manufacturer: Yageo; Power (Watts): 0.063W, 1/16W; .Checked PCB: used; Temperature Coefficient: ±100ppm/°C
U1 = MCIMX6Q5EYM10AC: IC MCU 32BIT ARM QUAD 624FCBGA; Manufacturer: Freescale Semiconductor; Core Processor: ARM® Cortex™-A9; Core Size: 32-Bit Quad-Core; Speed: 1.0GHz; Connectivity: CAN, EBI/EMI, ESAI, Ethernet, GPMI, I2C, MMC/SD, PCI, SATA, SPI, UART, USB, USB OTG; Peripherals: DMA, HDMI, I2S/SSI/AC97, MIPI CSI, MIMI DSI, MIPI HIS, PWM, WDT; Number of I /O: 224; Program Memory Type: External Program Memory; RAM Size: 256K x 8; Voltage - Supply (Vcc/Vdd): 0.925 V ~ 1.5 V; Oscillator Type: Internal; .Creator: MM; .Checked PCB: MM, checked by RF
U2-U5 = MT41J128M16HA-15E:D TR: IC DDR3 SDRAM 2GBIT 667MHZ 96BGA; Manufacturer: Micron Technology Inc; Format - Memory: RAM; Memory Size: 2G (128M x 16); Interface: Parallel; Voltage - Supply: 1.425 V ~ 1.575 V; .Creator: MM; .Checked PCB: RF, used by MM; .Checked SCH: MM, checked by RF

## Sheet [05] - CPU - PCIE, SATA.SchDoc
size A2; DocumentNumber: 5; SheetNumber: 5; SheetTotal: 20
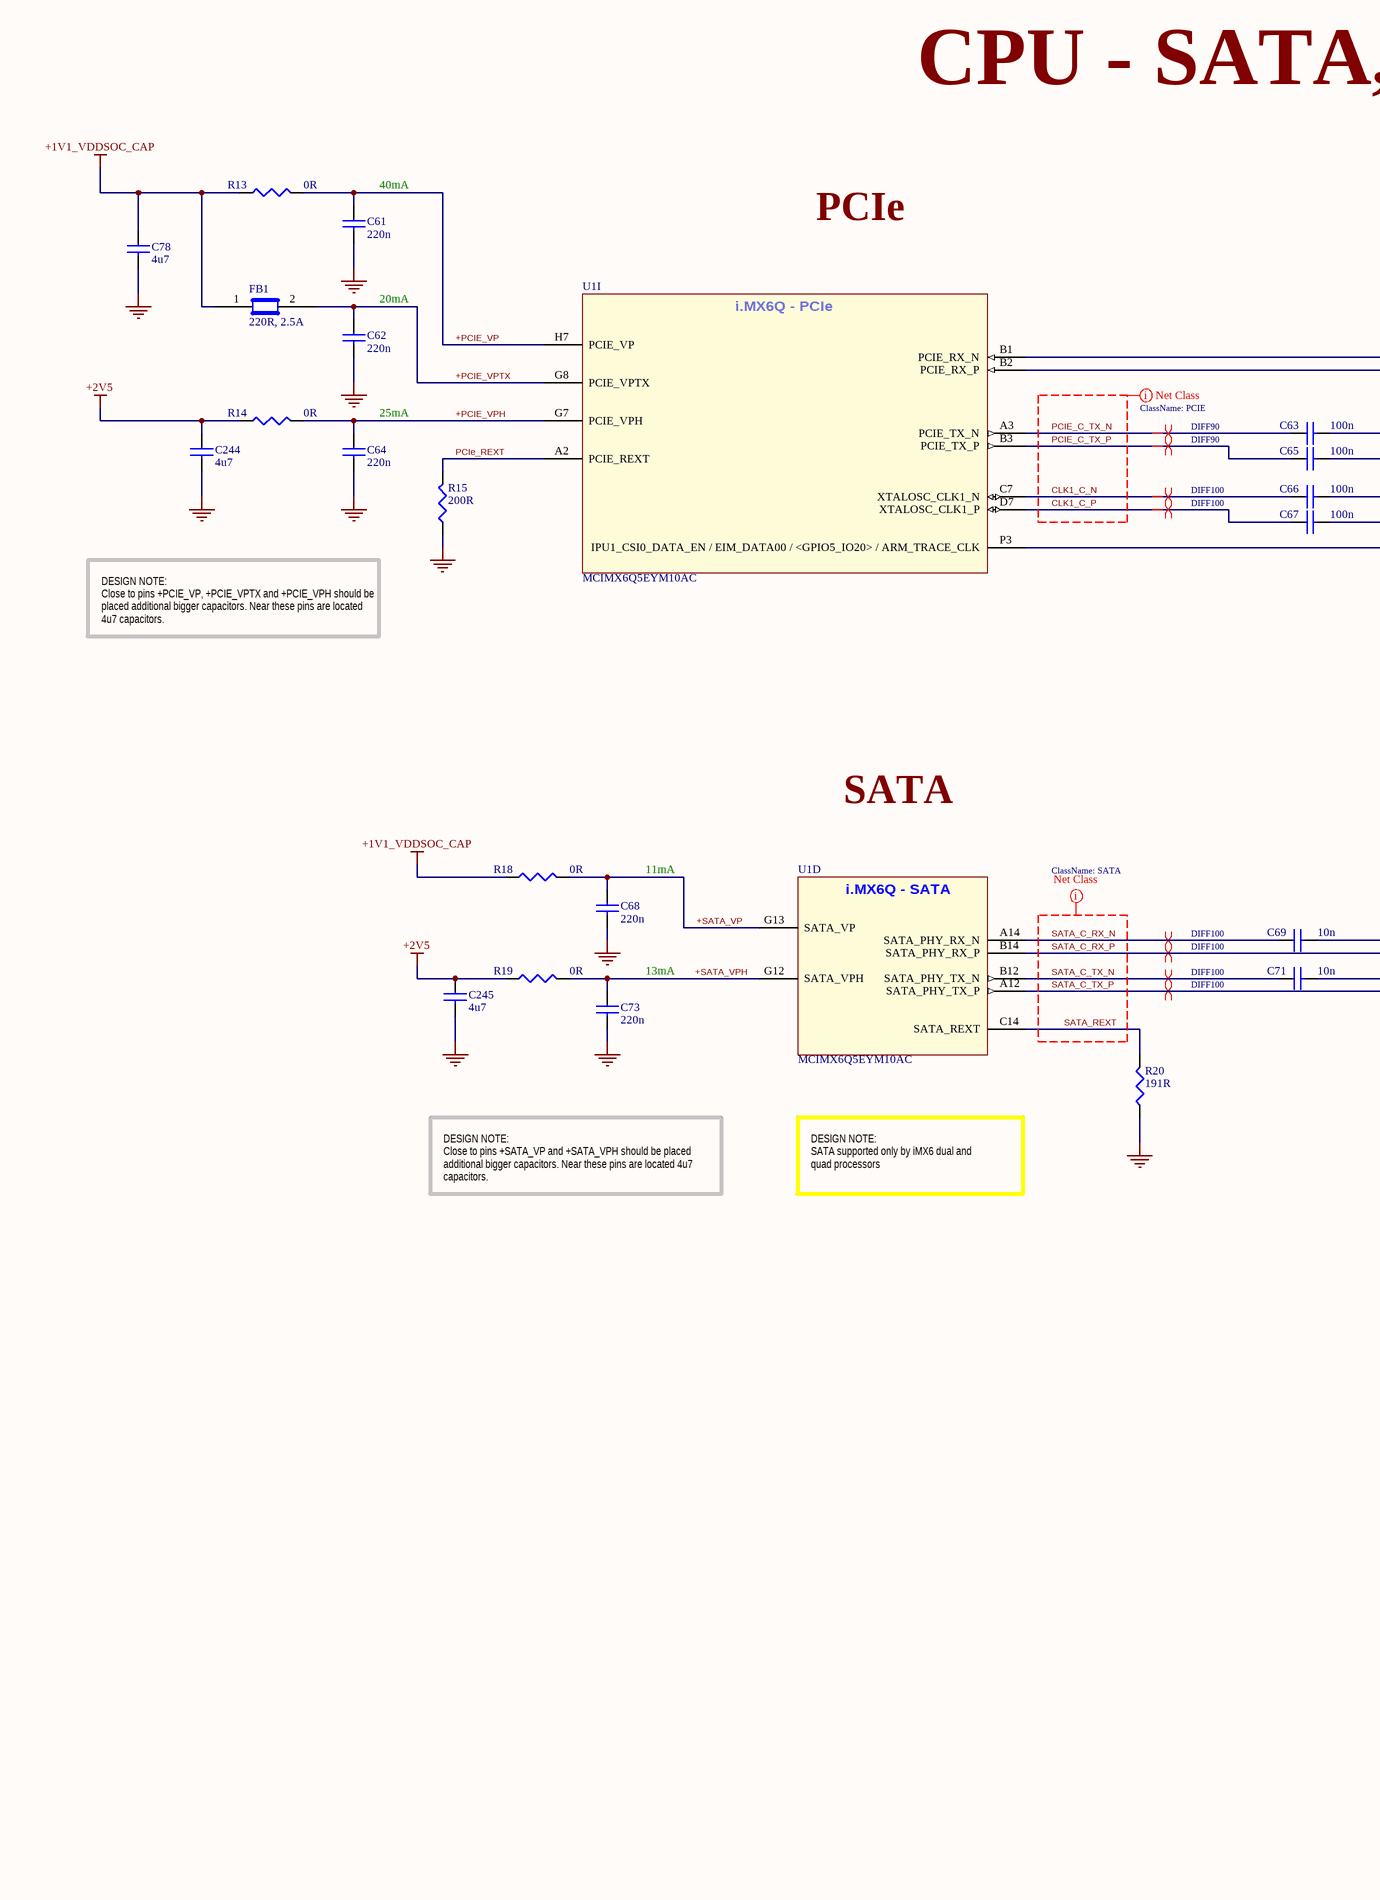
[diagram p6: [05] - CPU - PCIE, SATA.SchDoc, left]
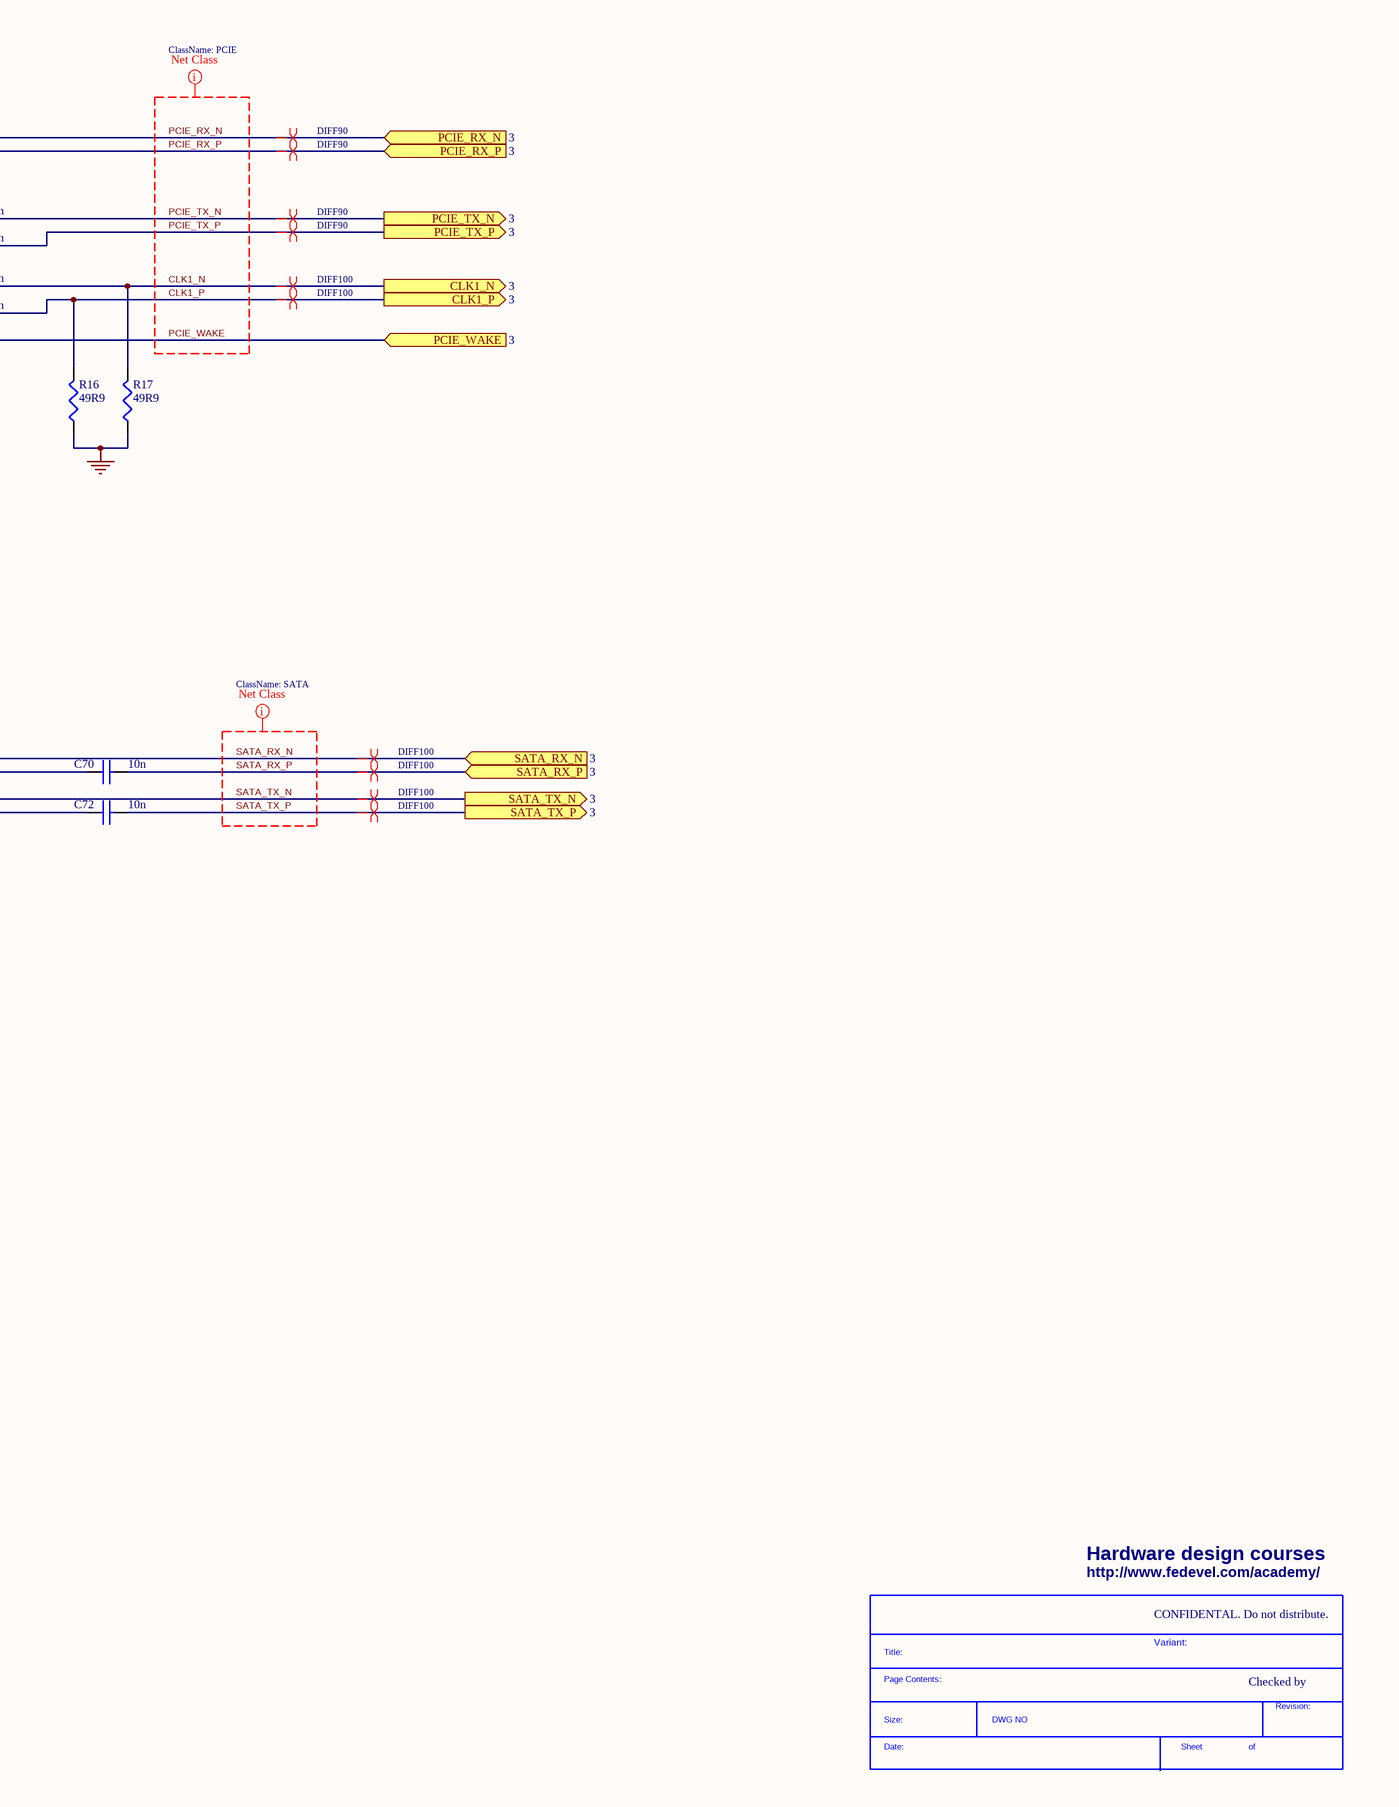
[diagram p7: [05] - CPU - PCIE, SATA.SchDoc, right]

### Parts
(Parts that share a designator on the sheet are numbered #1, #2 ... from top to bottom, then left to right.)
*#6  SDTitleBlock  (value not drawn)  (graphical)
C61  220n  [C0402]
C62  220n  [C0402]
C63  100n  [C0402]
C64  220n  [C0402]
C65  100n  [C0402]
C66  100n  [C0402]
C67  100n  [C0402]
C68  220n  [C0402]
C69  10n  [C0402]
C70  10n  [C0402]
C71  10n  [C0402]
C72  10n  [C0402]
C73  220n  [C0402]
C78  4u7  [C0402]
C244  4u7  [C0402]
C245  4u7  [C0402]
FB1  220R, 2.5A  [C0603]
R13  0R  [R0402]
R14  0R  [R0402]
R15  200R  [R0402]
R16  49R9  [R0402]
R17  49R9  [R0402]
R18  0R  [R0402]
R19  0R  [R0402]
R20  191R  [R0402]
U1  MCIMX6Q5EYM10AC  [PBGA624]  (parts D,I of 15)

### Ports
CLK1_N (out, see 3), CLK1_P (out, see 3), PCIE_RX_N (in, see 3), PCIE_RX_P (in, see 3), PCIE_TX_N (out, see 3), PCIE_TX_P (out, see 3), PCIE_WAKE (in, see 3), SATA_RX_N (in, see 3), SATA_RX_P (in, see 3), SATA_TX_N (out, see 3), SATA_TX_P (out, see 3)

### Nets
+1V1_VDDSOC_CAP: C78.1 FB1.1 R13.1 R18.1
+2V5: C244.1 C245.1 R14.1 R19.1
GND: C61.2 C62.2 C64.2 C68.2 C73.2 C78.2 C244.2 C245.2 R15.1 R16.1 R17.1 R20.1
+PCIE_VP: C61.1 R13.2 U1.H7(PCIE_VP)
+PCIE_VPH: C64.1 R14.2 U1.G7(PCIE_VPH)
+PCIE_VPTX: C62.1 FB1.2 U1.G8(PCIE_VPTX)
+SATA_VP: C68.1 R18.2 U1.G13(SATA_VP)
+SATA_VPH: C73.1 R19.2 U1.G12(SATA_VPH)
CLK1_C_N: C66.1 U1.C7(XTALOSC_CLK1_N)
CLK1_C_P: C67.1 U1.D7(XTALOSC_CLK1_P)
CLK1_N: C66.2 R17.2 ; port CLK1_N
CLK1_P: C67.2 R16.2 ; port CLK1_P
PCIE_C_TX_N: C63.1 U1.A3(PCIE_TX_N)
PCIE_C_TX_P: C65.1 U1.B3(PCIE_TX_P)
PCIe_REXT: R15.2 U1.A2(PCIE_REXT)
PCIE_RX_N: U1.B1(PCIE_RX_N) ; port PCIE_RX_N
PCIE_RX_P: U1.B2(PCIE_RX_P) ; port PCIE_RX_P
PCIE_TX_N: C63.2 ; port PCIE_TX_N
PCIE_TX_P: C65.2 ; port PCIE_TX_P
PCIE_WAKE: U1.P3(IPU1_CSI0_DATA_EN_/_EIM_DATA00_/_<GPIO5_IO20>_/_ARM_TRACE_CLK) ; port PCIE_WAKE
SATA_C_RX_N: C69.1 U1.A14(SATA_PHY_RX_N)
SATA_C_RX_P: C70.1 U1.B14(SATA_PHY_RX_P)
SATA_C_TX_N: C71.1 U1.B12(SATA_PHY_TX_N)
SATA_C_TX_P: C72.1 U1.A12(SATA_PHY_TX_P)
SATA_REXT: R20.2 U1.C14(SATA_REXT)
SATA_RX_N: C69.2 ; port SATA_RX_N
SATA_RX_P: C70.2 ; port SATA_RX_P
SATA_TX_N: C71.2 ; port SATA_TX_N
SATA_TX_P: C72.2 ; port SATA_TX_P

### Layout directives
differential pair; net class DIFF100: CLK1_C_N, CLK1_C_P, CLK1_N, CLK1_P, SATA_C_RX_N, SATA_C_RX_P, SATA_C_TX_N, SATA_C_TX_P, SATA_RX_N, SATA_RX_P, SATA_TX_N, SATA_TX_P
differential pair; net class DIFF90: PCIE_C_TX_N, PCIE_C_TX_P, PCIE_RX_N, PCIE_RX_P, PCIE_TX_N, PCIE_TX_P
net class PCIE: CLK1_C_N, CLK1_C_P, CLK1_N, CLK1_P, PCIE_C_TX_N, PCIE_C_TX_P, PCIE_RX_N, PCIE_RX_P, PCIE_TX_N, PCIE_TX_P, PCIE_WAKE
net class SATA: SATA_C_RX_N, SATA_C_RX_P, SATA_C_TX_N, SATA_C_TX_P, SATA_REXT, SATA_RX_N, SATA_RX_P, SATA_TX_N, SATA_TX_P

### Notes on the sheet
- CPU - SATA, PCIe
- (near C61) 40mA
- PCIe
- (near C62) 20mA
- (near C64) 25mA
- DESIGN NOTE:
  Close to pins +PCIE_VP, +PCIE_VPTX and +PCIE_VPH should be placed additional bigger capacitors. Near these pins are located 4u7 capacitors.
- SATA
- (near C68) 11mA
- 13mA
- DESIGN NOTE:
  Close to pins +SATA_VP and +SATA_VPH should be placed additional bigger capacitors. Near these pins are located 4u7 capacitors.
- DESIGN NOTE:
  SATA supported only by iMX6 dual and quad processors
- Hardware design courses
- http://www.fedevel.com/academy/
- CONFIDENTAL. Do not distribute.
- CLOCKS (CPU & PCIE)
- Variant:
- Checked by

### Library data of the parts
C61 C62 C64 C68 C73 = C1005X5R1E224M: as C3 on sheet [04] - CPU - DDR3, DDR3 MEM
C63 C65-C67 = C1005X5R1H104K: as C7 on sheet [04] - CPU - DDR3, DDR3 MEM
C69-C72 = C1005X7R1H103K: CAP CER 10000PF 50V 10% X7R 0402; Manufacturer: TDK Corporation; Value: 10nF; .Checked PCB: RF
C78 C244 C245 = C1005X5R1A475M: CAP CER 4.7UF 10V 20% X5R 0402; Manufacturer: TDK Corporation; Capacitance: 4.7µF; .Checked PCB: RF
FB1 = BLM18SG221TN1D: FERRITE CHIP 220 OHM 2500MA 0603; Manufacturer: Murata Electronics North America; Impedance @ Frequency: 220 Ohm @ 100MHz; DC Resistance (DCR): 40 mOhm Max; Filter Type: Differential Mode - Single; Number of Lines: 1; .Checked PCB: RF
R13 R14 R18 R19 = RC0402JR-070RL: RES 0.0 OHM 1/16W 0402 SMD; Manufacturer: Yageo; Resistance (Ohms): 0.0; Power (Watts): 0.063W, 1/16W; Tolerance: Jumper; .Checked PCB: used
R15 = CRCW0402200RFKED: as R2 on sheet [04] - CPU - DDR3, DDR3 MEM
R16 R17 = RC0402FR-0749R9L: RES 49.9 OHM 1/16W 1% 0402 SMD; Manufacturer: Yageo; Resistance (Ohms): 49.9; Power (Watts): 0.063W, 1/16W; Value: 49.9R; .Checked PCB: used; Temperature Coefficient: ±100ppm/°C
R20 = CRCW0402191RFKED: RES 191 OHM 1/16W 1% 0402 SMD; Manufacturer: Vishay Dale; Resistance (Ohms): 191; Power (Watts): 0.063W, 1/16W; Temperature Coefficient: ±100ppm/°C; .Creator: MM; .Checked PCB: RF, used by MM; .Checked SCH: MM, checked by RF
U1 = MCIMX6Q5EYM10AC: as U1 on sheet [04] - CPU - DDR3, DDR3 MEM

## Sheet [06] - CPU - HDMI, LVDS.SchDoc
size A2; DocumentNumber: 6; SheetNumber: 6; SheetTotal: 20
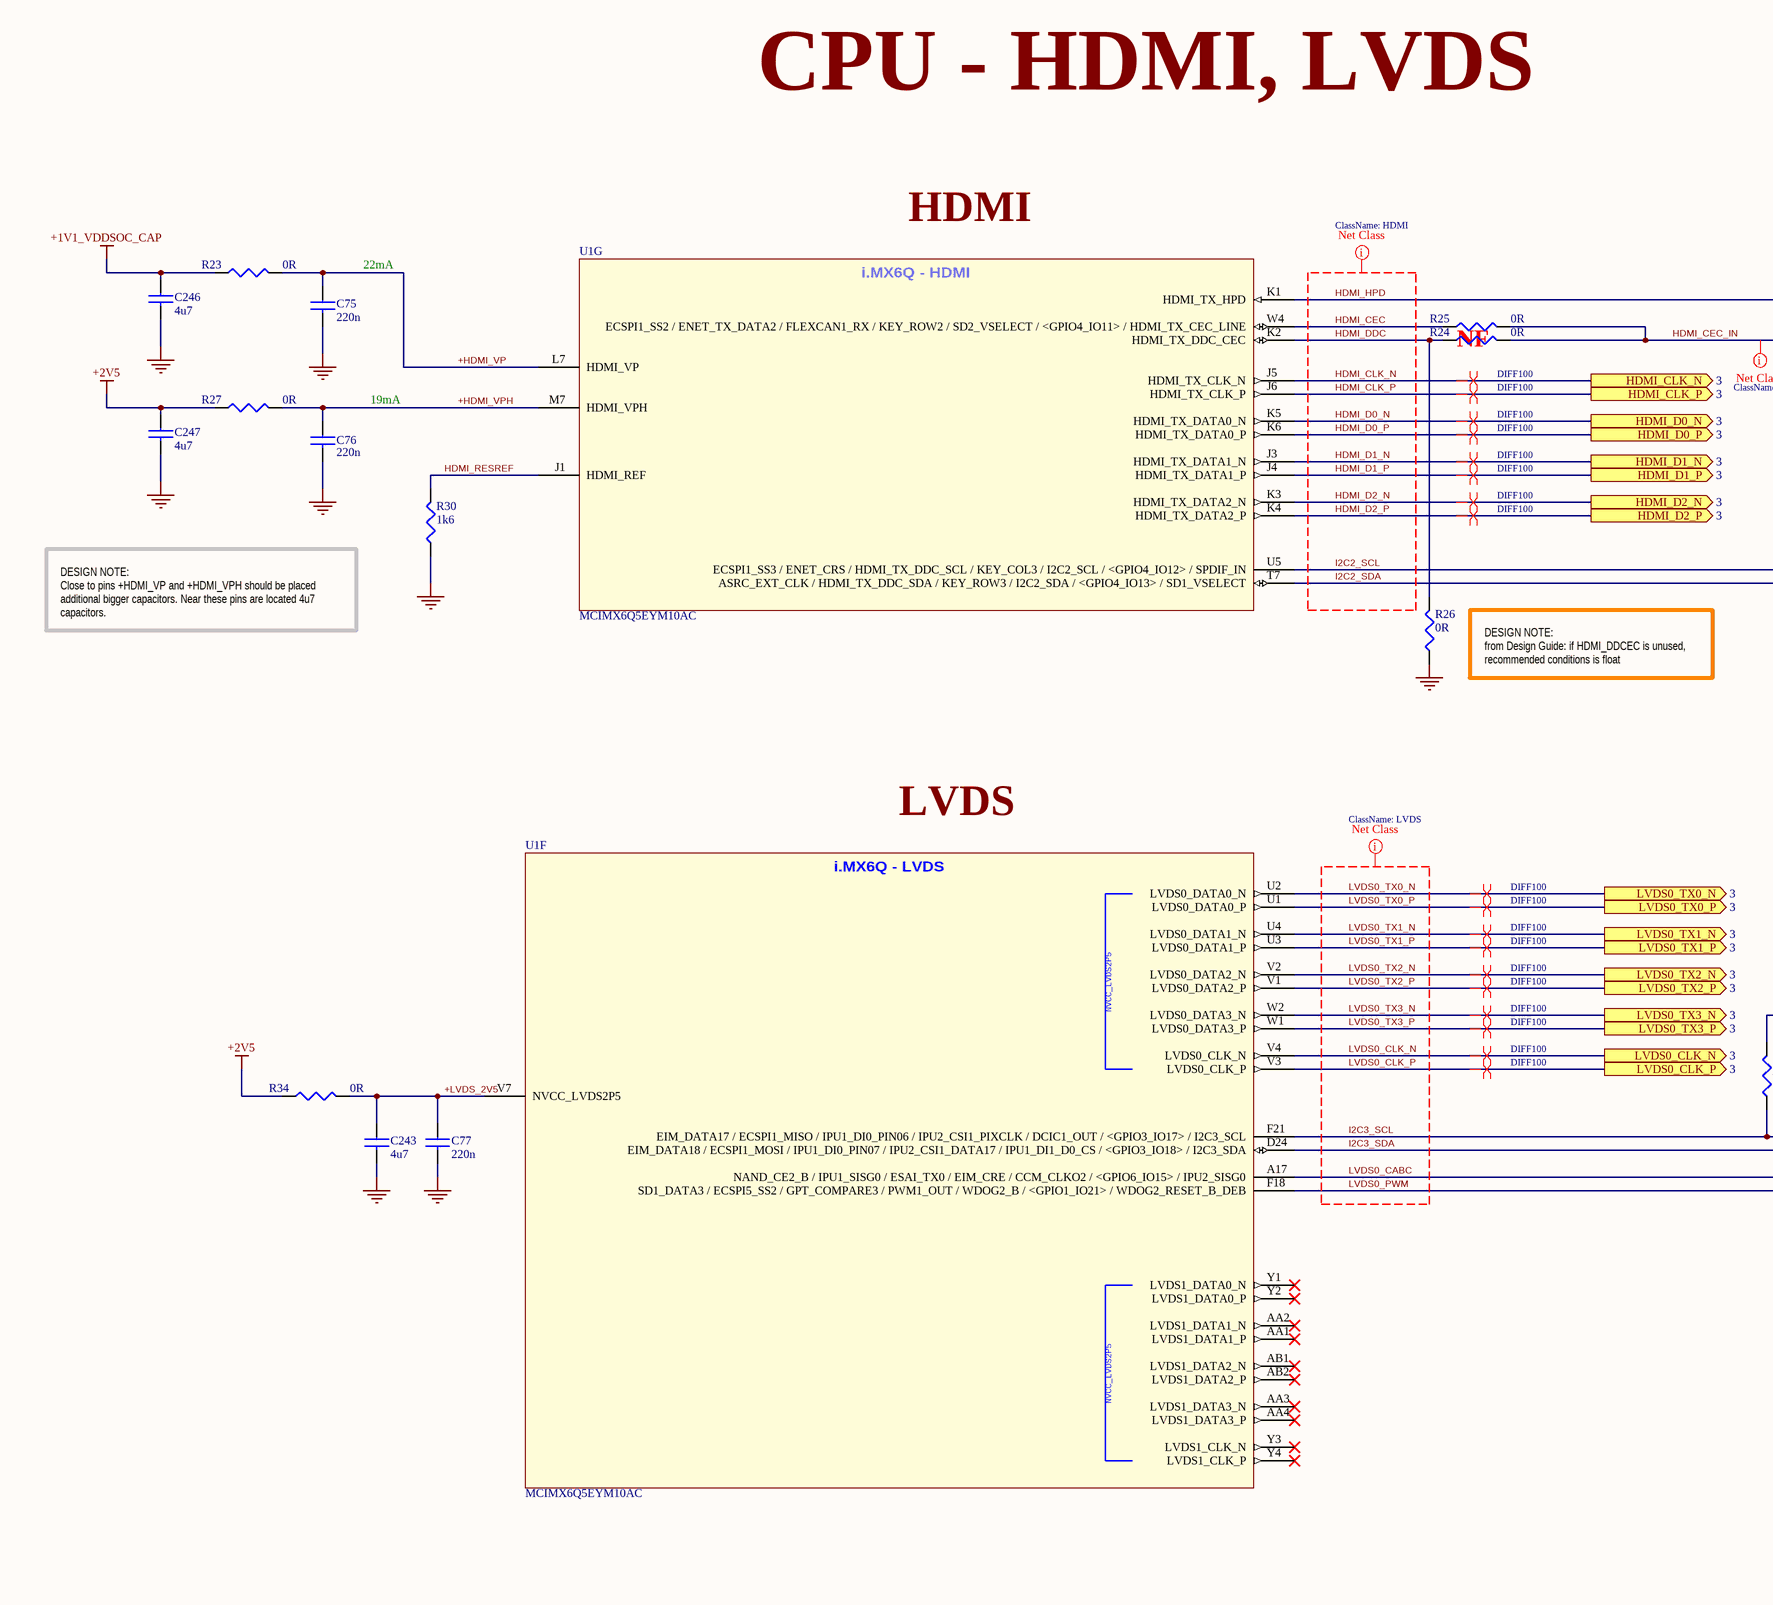
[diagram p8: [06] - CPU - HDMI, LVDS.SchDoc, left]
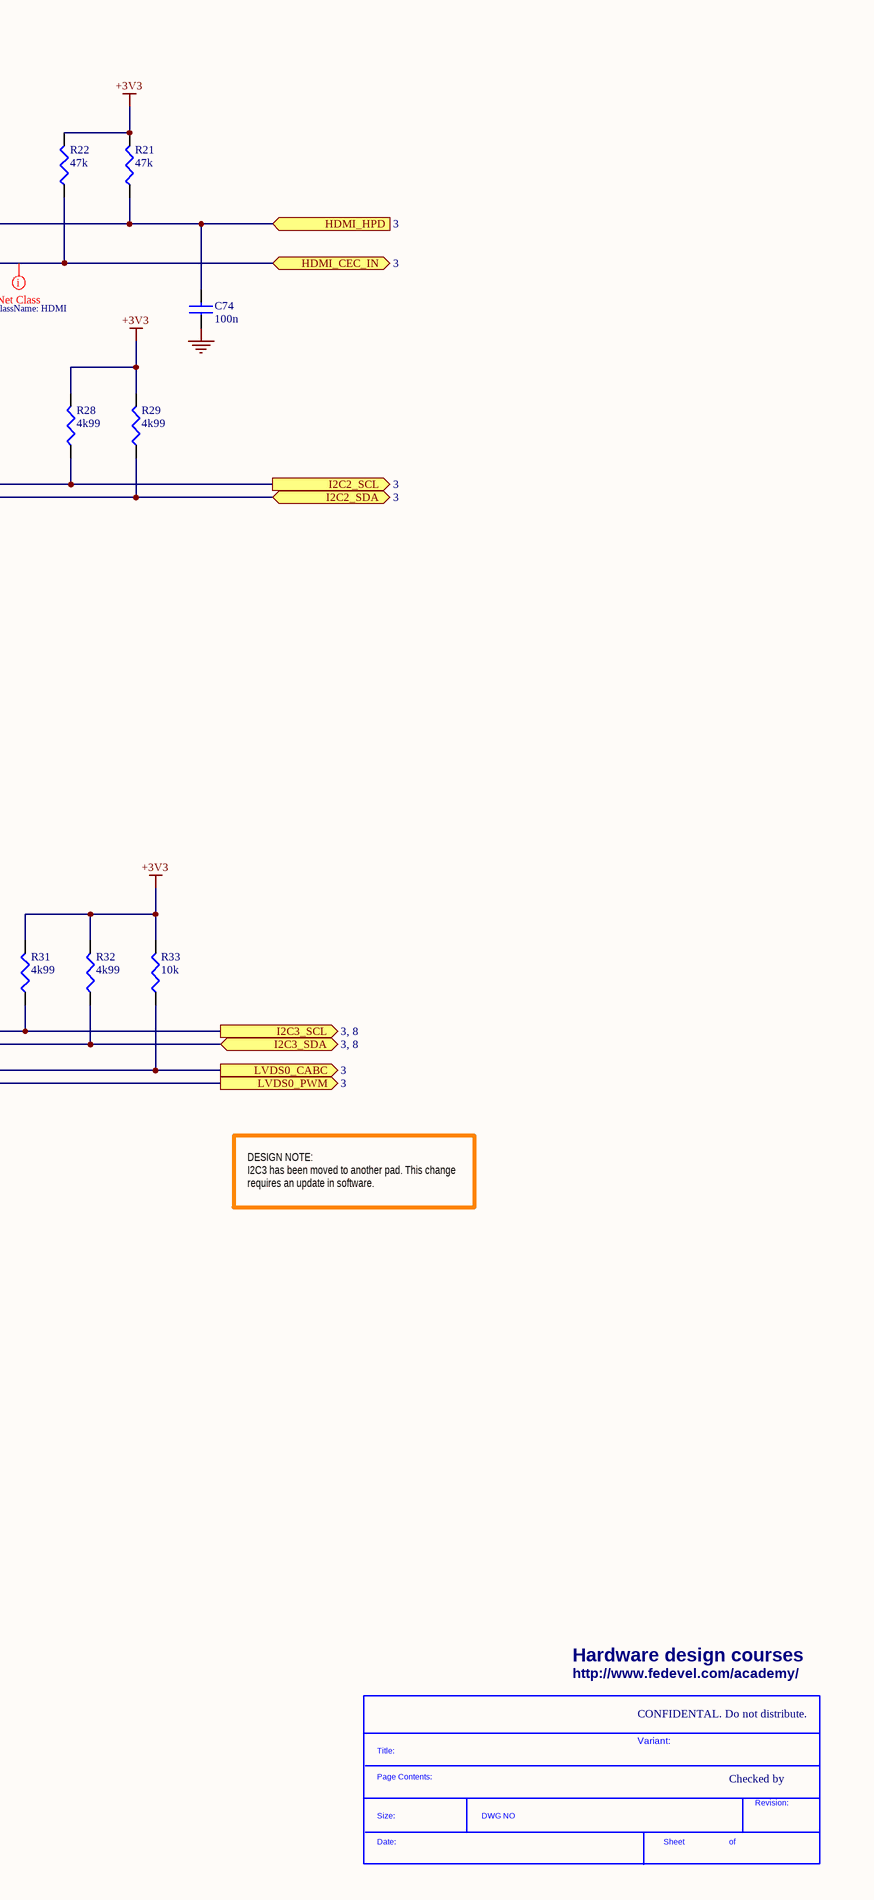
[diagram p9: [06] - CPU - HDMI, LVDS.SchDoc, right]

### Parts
(Parts that share a designator on the sheet are numbered #1, #2 ... from top to bottom, then left to right.)
*#7  SDTitleBlock  (value not drawn)  (graphical)
C74  100n  [C0402]
C75  220n  [C0402]
C76  220n  [C0402]
C77  220n  [C0402]
C243  4u7  [C0402]
C246  4u7  [C0402]
C247  4u7  [C0402]
R21  47k  [R0402]
R22  47k  [R0402]
R23  0R  [R0402]
R24  0R  [R0402]
R25  0R  [R0402]
R26  0R  [R0402]
R27  0R  [R0402]
R28  4k99  [R0402]
R29  4k99  [R0402]
R30  1k6  [R0402]
R31  4k99  [R0402]
R32  4k99  [R0402]
R33  10k  [R0402]
R34  0R  [R0402]
U1  MCIMX6Q5EYM10AC  [PBGA624]  (parts F,G of 15)

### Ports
HDMI_CEC_IN (bidir, see 3), HDMI_CLK_N (out, see 3), HDMI_CLK_P (out, see 3), HDMI_D0_N (out, see 3), HDMI_D0_P (out, see 3), HDMI_D1_N (out, see 3), HDMI_D1_P (out, see 3), HDMI_D2_N (out, see 3), HDMI_D2_P (out, see 3), HDMI_HPD (in, see 3), I2C2_SCL (out, see 3), I2C2_SDA (bidir, see 3), I2C3_SCL (see 3, 8), I2C3_SDA (bidir, see 3, 8), LVDS0_CABC (out, see 3), LVDS0_CLK_N (out, see 3), LVDS0_CLK_P (out, see 3), LVDS0_PWM (out, see 3), LVDS0_TX0_N (out, see 3), LVDS0_TX0_P (out, see 3), LVDS0_TX1_N (out, see 3), LVDS0_TX1_P (out, see 3), LVDS0_TX2_N (out, see 3), LVDS0_TX2_P (out, see 3), LVDS0_TX3_N (out, see 3), LVDS0_TX3_P (out, see 3)

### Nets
+1V1_VDDSOC_CAP: C246.1 R23.1
+2V5: C247.1 R27.1 R34.1
+3V3: R21.2 R22.2 R28.2 R29.2 R31.2 R32.2 R33.2
GND: C74.1 C75.2 C76.2 C77.2 C243.2 C246.2 C247.2 R26.1 R30.1
+HDMI_VP: C75.1 R23.2 U1.L7(HDMI_VP)
+HDMI_VPH: C76.1 R27.2 U1.M7(HDMI_VPH)
+LVDS_2V5: C77.1 C243.1 R34.2 U1.V7(NVCC_LVDS2P5)
HDMI_CEC: R25.1 U1.W4(ECSPI1_SS2_/_ENET_TX_DATA2_/_FLEXCAN1_RX_/_KEY_ROW2_/_SD2_VSELECT_/_<GPIO4_IO11>_/_HDMI_TX_CEC_LINE)
HDMI_CEC_IN: R22.1 R24.2 R25.2 ; port HDMI_CEC_IN
HDMI_CLK_N: U1.J5(HDMI_TX_CLK_N) ; port HDMI_CLK_N
HDMI_CLK_P: U1.J6(HDMI_TX_CLK_P) ; port HDMI_CLK_P
HDMI_D0_N: U1.K5(HDMI_TX_DATA0_N) ; port HDMI_D0_N
HDMI_D0_P: U1.K6(HDMI_TX_DATA0_P) ; port HDMI_D0_P
HDMI_D1_N: U1.J3(HDMI_TX_DATA1_N) ; port HDMI_D1_N
HDMI_D1_P: U1.J4(HDMI_TX_DATA1_P) ; port HDMI_D1_P
HDMI_D2_N: U1.K3(HDMI_TX_DATA2_N) ; port HDMI_D2_N
HDMI_D2_P: U1.K4(HDMI_TX_DATA2_P) ; port HDMI_D2_P
HDMI_DDC: R24.1 R26.2 U1.K2(HDMI_TX_DDC_CEC)
HDMI_HPD: C74.2 R21.1 U1.K1(HDMI_TX_HPD) ; port HDMI_HPD
HDMI_RESREF: R30.2 U1.J1(HDMI_REF)
I2C2_SCL: R28.1 U1.U5(ECSPI1_SS3_/_ENET_CRS_/_HDMI_TX_DDC_SCL_/_KEY_COL3_/_I2C2_SCL_/_<GPIO4_IO12>_/_SPDIF_IN) ; port I2C2_SCL
I2C2_SDA: R29.1 U1.T7(ASRC_EXT_CLK_/_HDMI_TX_DDC_SDA_/_KEY_ROW3_/_I2C2_SDA_/_<GPIO4_IO13>_/_SD1_VSELECT) ; port I2C2_SDA
I2C3_SCL: R31.1 U1.F21(EIM_DATA17_/_ECSPI1_MISO_/_IPU1_DI0_PIN06_/_IPU2_CSI1_PIXCLK_/_DCIC1_OUT_/_<GPIO3_IO17>_/_I2C3_SCL) ; port I2C3_SCL
I2C3_SDA: R32.1 U1.D24(EIM_DATA18_/_ECSPI1_MOSI_/_IPU1_DI0_PIN07_/_IPU2_CSI1_DATA17_/_IPU1_DI1_D0_CS_/_<GPIO3_IO18>_/_I2C3_SDA) ; port I2C3_SDA
LVDS0_CABC: R33.1 U1.A17(NAND_CE2_B_/_IPU1_SISG0_/_ESAI_TX0_/_EIM_CRE_/_CCM_CLKO2_/_<GPIO6_IO15>_/_IPU2_SISG0) ; port LVDS0_CABC
LVDS0_CLK_N: U1.V4(LVDS0_CLK_N) ; port LVDS0_CLK_N
LVDS0_CLK_P: U1.V3(LVDS0_CLK_P) ; port LVDS0_CLK_P
LVDS0_PWM: U1.F18(SD1_DATA3_/_ECSPI5_SS2_/_GPT_COMPARE3_/_PWM1_OUT_/_WDOG2_B_/_<GPIO1_IO21>_/_WDOG2_RESET_B_DEB) ; port LVDS0_PWM
LVDS0_TX0_N: U1.U2(LVDS0_DATA0_N) ; port LVDS0_TX0_N
LVDS0_TX0_P: U1.U1(LVDS0_DATA0_P) ; port LVDS0_TX0_P
LVDS0_TX1_N: U1.U4(LVDS0_DATA1_N) ; port LVDS0_TX1_N
LVDS0_TX1_P: U1.U3(LVDS0_DATA1_P) ; port LVDS0_TX1_P
LVDS0_TX2_N: U1.V2(LVDS0_DATA2_N) ; port LVDS0_TX2_N
LVDS0_TX2_P: U1.V1(LVDS0_DATA2_P) ; port LVDS0_TX2_P
LVDS0_TX3_N: U1.W2(LVDS0_DATA3_N) ; port LVDS0_TX3_N
LVDS0_TX3_P: U1.W1(LVDS0_DATA3_P) ; port LVDS0_TX3_P

Not connected (* = marked no-connect by the designer): U1 AA1(LVDS1_DATA1_P)* AA2(LVDS1_DATA1_N)* AA3(LVDS1_DATA3_N)* AA4(LVDS1_DATA3_P)* AB1(LVDS1_DATA2_N)* AB2(LVDS1_DATA2_P)* Y1(LVDS1_DATA0_N)* Y2(LVDS1_DATA0_P)* Y3(LVDS1_CLK_N)* Y4(LVDS1_CLK_P)*

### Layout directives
differential pair; net class DIFF100: HDMI_CLK_N, HDMI_CLK_P, HDMI_D0_N, HDMI_D0_P, HDMI_D1_N, HDMI_D1_P, HDMI_D2_N, HDMI_D2_P, LVDS0_CLK_N, LVDS0_CLK_P, LVDS0_TX0_N, LVDS0_TX0_P, LVDS0_TX1_N, LVDS0_TX1_P, LVDS0_TX2_N, LVDS0_TX2_P, LVDS0_TX3_N, LVDS0_TX3_P
net class LVDS: I2C3_SCL, I2C3_SDA, LVDS0_CABC, LVDS0_CLK_N, LVDS0_CLK_P, LVDS0_PWM, LVDS0_TX0_N, LVDS0_TX0_P, LVDS0_TX1_N, LVDS0_TX1_P, LVDS0_TX2_N, LVDS0_TX2_P, LVDS0_TX3_N, LVDS0_TX3_P
net class HDMI: HDMI_CEC, HDMI_CEC_IN, HDMI_CLK_N, HDMI_CLK_P, HDMI_D0_N, HDMI_D0_P, HDMI_D1_N, HDMI_D1_P, HDMI_D2_N, HDMI_D2_P, HDMI_DDC, HDMI_HPD, I2C2_SCL, I2C2_SDA

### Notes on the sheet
- CPU - HDMI, LVDS
- HDMI
- (near C75) 22mA
- NF
- 19mA
- DESIGN NOTE:
  Close to pins +HDMI_VP and +HDMI_VPH should be placed additional bigger capacitors. Near these pins are located 4u7 capacitors.
- DESIGN NOTE:
  from Design Guide: if HDMI_DDCEC is unused, recommended conditions is float
- LVDS
- DESIGN NOTE:
  I2C3 has been moved to another pad. This change requires an update in software.
- Hardware design courses
- http://www.fedevel.com/academy/
- CONFIDENTAL. Do not distribute.
- Variant:
- Checked by

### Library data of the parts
C74 = C1005X5R1H104K: as C7 on sheet [04] - CPU - DDR3, DDR3 MEM
C75-C77 = C1005X5R1E224M: as C3 on sheet [04] - CPU - DDR3, DDR3 MEM
C243 C246 C247 = C1005X5R1A475M: as C78 on sheet [05] - CPU - PCIE, SATA
R21 R22 = RC0402FR-0747KL: RES 47.0K OHM 1/16W 1% 0402 SMD; Manufacturer: Yageo; Power (Watts): 0.063W, 1/16W; .Checked PCB: used; Temperature Coefficient: ±100ppm/°C
R23-R27 R34 = RC0402JR-070RL: as R13 on sheet [05] - CPU - PCIE, SATA
R28 R29 R31 R32 = RMCF0402FT4K99: RES TF 4.99K OHM 1% 1/16W 0402; Manufacturer: Stackpole Electronics Inc; Power (Watts): 0.063W, 1/16W; .Checked PCB: used; Temperature Coefficient: ±100ppm/°C
R30 = ERJ-2RKF1601X: RES 1.6K OHM 1/10W 1% 0402 SMD; Manufacturer: Panasonic Electronic Components; Power (Watts): 0.1W, 1/10W; Temperature Coefficient: ±100ppm/°C; .Creator: MM; .Checked PCB: RF, used by MM; .Checked SCH: MM, checked by RF
R33 = RC0402FR-0710KL: as R6 on sheet [04] - CPU - DDR3, DDR3 MEM
U1 = MCIMX6Q5EYM10AC: as U1 on sheet [04] - CPU - DDR3, DDR3 MEM

## Sheet [07] - CPU - USB, ETHERNET.SchDoc
size A2; DocumentNumber: 7; SheetNumber: 7; SheetTotal: 20
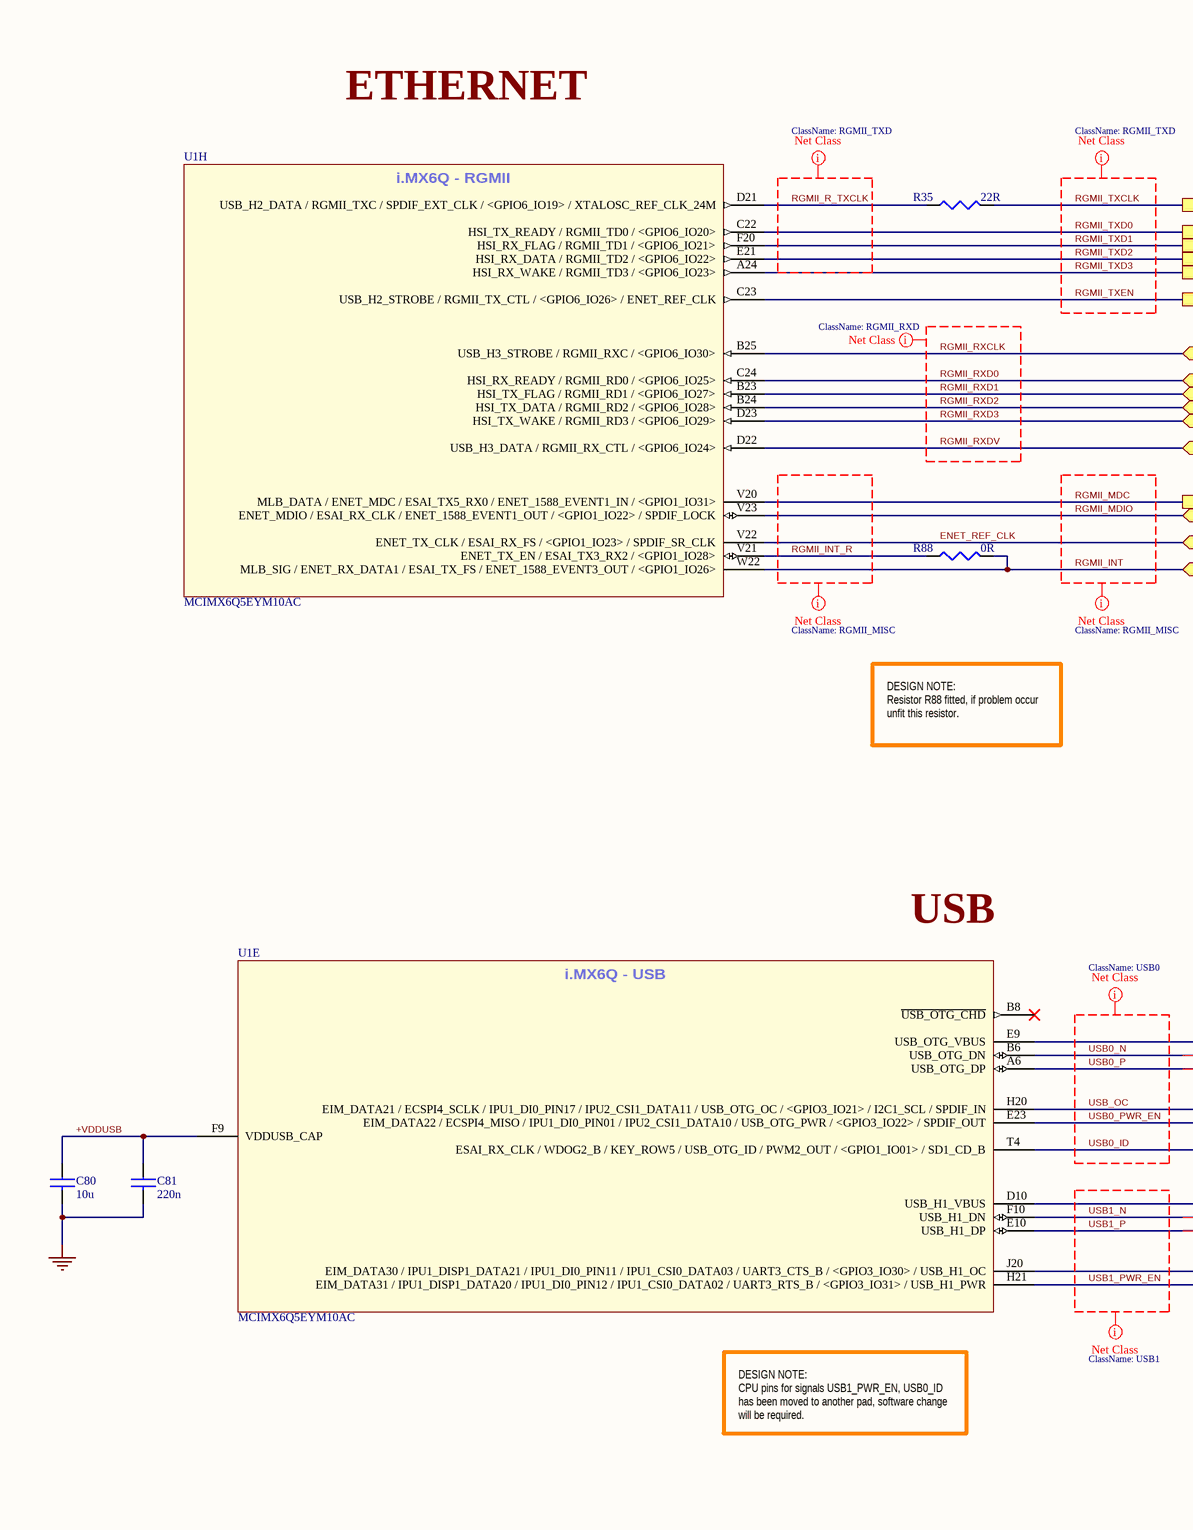
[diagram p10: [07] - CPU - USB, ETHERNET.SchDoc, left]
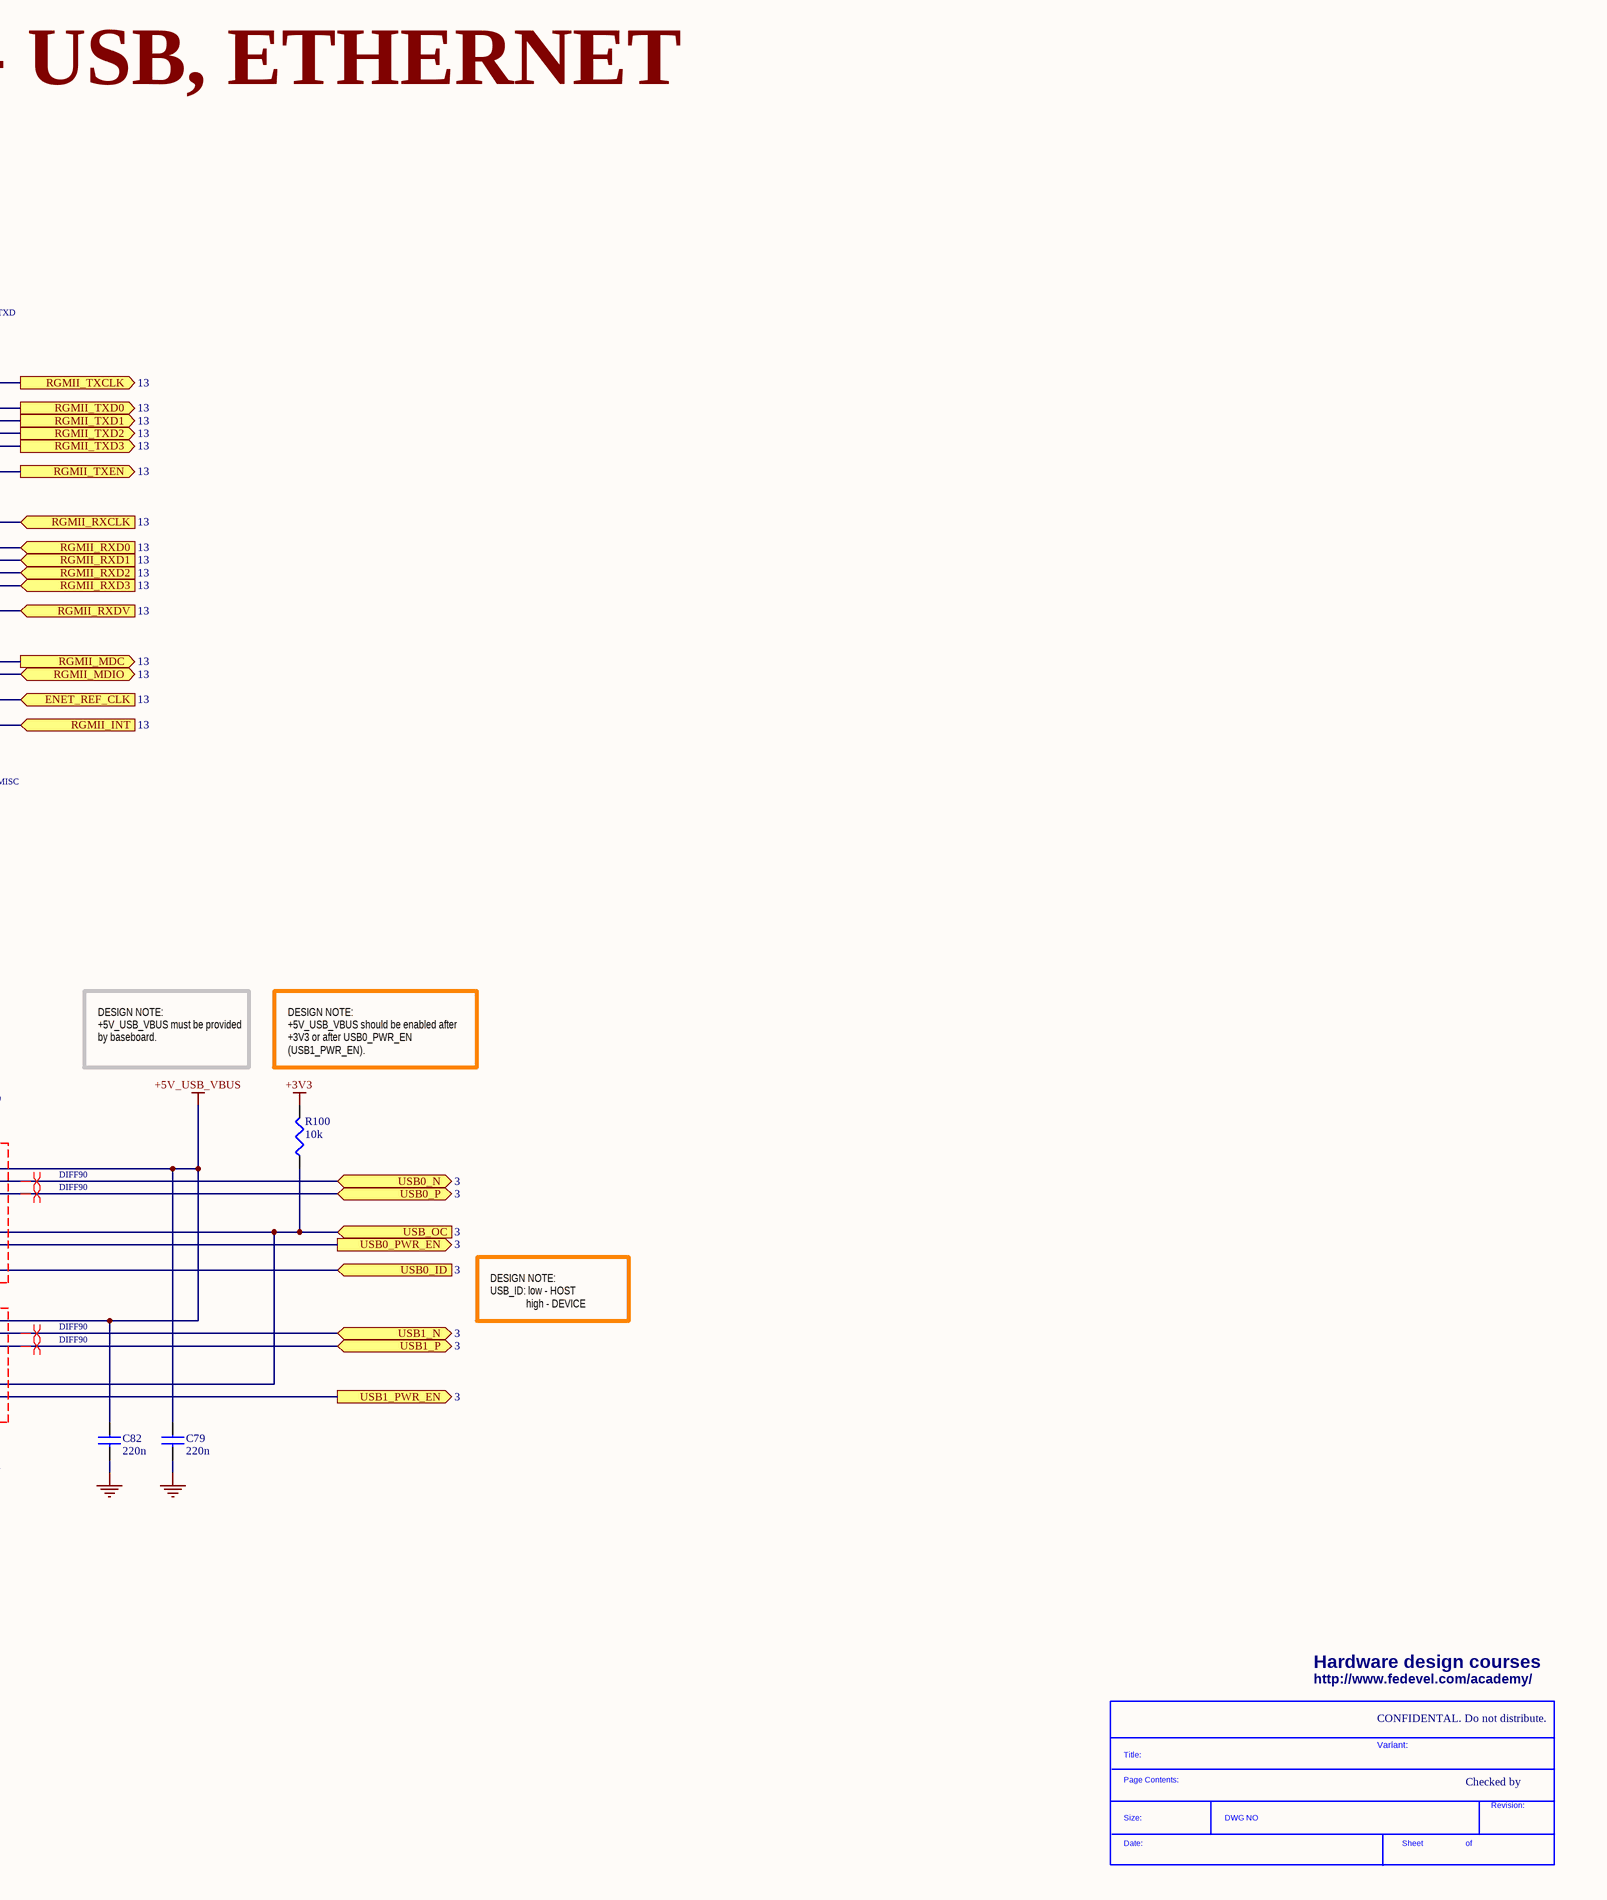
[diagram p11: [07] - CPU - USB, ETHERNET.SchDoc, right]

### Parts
(Parts that share a designator on the sheet are numbered #1, #2 ... from top to bottom, then left to right.)
*#8  SDTitleBlock  (value not drawn)  (graphical)
C79  220n  [C0402]
C80  10u  [C0603]
C81  220n  [C0402]
C82  220n  [C0402]
R35  22R  [R0402]
R88  0R  [R0402]
R100  10k  [R0402]
U1  MCIMX6Q5EYM10AC  [PBGA624]  (parts E,H of 15)

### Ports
ENET_REF_CLK (in, see 13), RGMII_INT (in, see 13), RGMII_MDC (out, see 13), RGMII_MDIO (bidir, see 13), RGMII_RXCLK (in, see 13), RGMII_RXD0 (in, see 13), RGMII_RXD1 (in, see 13), RGMII_RXD2 (in, see 13), RGMII_RXD3 (in, see 13), RGMII_RXDV (in, see 13), RGMII_TXCLK (out, see 13), RGMII_TXD0 (out, see 13), RGMII_TXD1 (out, see 13), RGMII_TXD2 (out, see 13), RGMII_TXD3 (out, see 13), RGMII_TXEN (out, see 13), USB0_ID (in, see 3), USB0_N (bidir, see 3), USB0_P (bidir, see 3), USB0_PWR_EN (out, see 3), USB1_N (bidir, see 3), USB1_P (bidir, see 3), USB1_PWR_EN (out, see 3), USB_OC (in, see 3)

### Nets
+3V3: R100.2
+5V_USB_VBUS: C79.1 C82.1 U1.D10(USB_H1_VBUS) U1.E9(USB_OTG_VBUS)
GND: C79.2 C80.2 C81.2 C82.2
+VDDUSB: C80.1 C81.1 U1.F9(VDDUSB_CAP)
ENET_REF_CLK: U1.V22(ENET_TX_CLK_/_ESAI_RX_FS_/_<GPIO1_IO23>_/_SPDIF_SR_CLK) ; port ENET_REF_CLK
RGMII_INT: R88.2 U1.W22(MLB_SIG_/_ENET_RX_DATA1_/_ESAI_TX_FS_/_ENET_1588_EVENT3_OUT_/_<GPIO1_IO26>) ; port RGMII_INT
RGMII_INT_R: R88.1 U1.V21(ENET_TX_EN_/_ESAI_TX3_RX2_/_<GPIO1_IO28>)
RGMII_MDC: U1.V20(MLB_DATA_/_ENET_MDC_/_ESAI_TX5_RX0_/_ENET_1588_EVENT1_IN_/_<GPIO1_IO31>) ; port RGMII_MDC
RGMII_MDIO: U1.V23(ENET_MDIO_/_ESAI_RX_CLK_/_ENET_1588_EVENT1_OUT_/_<GPIO1_IO22>_/_SPDIF_LOCK) ; port RGMII_MDIO
RGMII_R_TXCLK: R35.1 U1.D21(USB_H2_DATA_/_RGMII_TXC_/_SPDIF_EXT_CLK_/_<GPIO6_IO19>_/_XTALOSC_REF_CLK_24M)
RGMII_RXCLK: U1.B25(USB_H3_STROBE_/_RGMII_RXC_/_<GPIO6_IO30>) ; port RGMII_RXCLK
RGMII_RXD0: U1.C24(HSI_RX_READY_/_RGMII_RD0_/_<GPIO6_IO25>) ; port RGMII_RXD0
RGMII_RXD1: U1.B23(HSI_TX_FLAG_/_RGMII_RD1_/_<GPIO6_IO27>) ; port RGMII_RXD1
RGMII_RXD2: U1.B24(HSI_TX_DATA_/_RGMII_RD2_/_<GPIO6_IO28>) ; port RGMII_RXD2
RGMII_RXD3: U1.D23(HSI_TX_WAKE_/_RGMII_RD3_/_<GPIO6_IO29>) ; port RGMII_RXD3
RGMII_RXDV: U1.D22(USB_H3_DATA_/_RGMII_RX_CTL_/_<GPIO6_IO24>) ; port RGMII_RXDV
RGMII_TXCLK: R35.2 ; port RGMII_TXCLK
RGMII_TXD0: U1.C22(HSI_TX_READY_/_RGMII_TD0_/_<GPIO6_IO20>) ; port RGMII_TXD0
RGMII_TXD1: U1.F20(HSI_RX_FLAG_/_RGMII_TD1_/_<GPIO6_IO21>) ; port RGMII_TXD1
RGMII_TXD2: U1.E21(HSI_RX_DATA_/_RGMII_TD2_/_<GPIO6_IO22>) ; port RGMII_TXD2
RGMII_TXD3: U1.A24(HSI_RX_WAKE_/_RGMII_TD3_/_<GPIO6_IO23>) ; port RGMII_TXD3
RGMII_TXEN: U1.C23(USB_H2_STROBE_/_RGMII_TX_CTL_/_<GPIO6_IO26>_/_ENET_REF_CLK) ; port RGMII_TXEN
USB0_ID: U1.T4(ESAI_RX_CLK_/_WDOG2_B_/_KEY_ROW5_/_USB_OTG_ID_/_PWM2_OUT_/_<GPIO1_IO01>_/_SD1_CD_B) ; port USB0_ID
USB0_N: U1.B6(USB_OTG_DN) ; port USB0_N
USB0_P: U1.A6(USB_OTG_DP) ; port USB0_P
USB0_PWR_EN: U1.E23(EIM_DATA22_/_ECSPI4_MISO_/_IPU1_DI0_PIN01_/_IPU2_CSI1_DATA10_/_USB_OTG_PWR_/_<GPIO3_IO22>_/_SPDIF_OUT) ; port USB0_PWR_EN
USB1_N: U1.F10(USB_H1_DN) ; port USB1_N
USB1_P: U1.E10(USB_H1_DP) ; port USB1_P
USB1_PWR_EN: U1.H21(EIM_DATA31_/_IPU1_DISP1_DATA20_/_IPU1_DI0_PIN12_/_IPU1_CSI0_DATA02_/_UART3_RTS_B_/_<GPIO3_IO31>_/_USB_H1_PWR) ; port USB1_PWR_EN
USB_OC: R100.1 U1.H20(EIM_DATA21_/_ECSPI4_SCLK_/_IPU1_DI0_PIN17_/_IPU2_CSI1_DATA11_/_USB_OTG_OC_/_<GPIO3_IO21>_/_I2C1_SCL_/_SPDIF_IN) U1.J20(EIM_DATA30_/_IPU1_DISP1_DATA21_/_IPU1_DI0_PIN11_/_IPU1_CSI0_DATA03_/_UART3_CTS_B_/_<GPIO3_IO30>_/_USB_H1_OC) ; port USB_OC

Not connected (* = marked no-connect by the designer): U1 B8(~{USB_OTG_CHD})*

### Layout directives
net class RGMII_MISC: RGMII_INT, RGMII_INT_R, RGMII_MDC, RGMII_MDIO
differential pair; net class DIFF90: USB0_N, USB0_P, USB1_N, USB1_P
net class USB0: USB0_ID, USB0_N, USB0_P, USB0_PWR_EN, USB_OC
net class USB1: USB1_N, USB1_P, USB1_PWR_EN
net class RGMII_TXD: RGMII_R_TXCLK, RGMII_TXCLK, RGMII_TXD0, RGMII_TXD1, RGMII_TXD2, RGMII_TXD3, RGMII_TXEN
net class RGMII_RXD: RGMII_RXCLK, RGMII_RXD0, RGMII_RXD1, RGMII_RXD2, RGMII_RXD3, RGMII_RXDV

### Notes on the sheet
- CPU - USB, ETHERNET
- ETHERNET
- DESIGN NOTE:
  Resistor R88 fitted, if problem occur unfit this resistor.
- USB
- DESIGN NOTE:
  +5V_USB_VBUS must be provided by baseboard.
- DESIGN NOTE:
  +5V_USB_VBUS should be enabled after +3V3 or after USB0_PWR_EN (USB1_PWR_EN).
- DESIGN NOTE:
  USB_ID: low - HOST
  high - DEVICE
- DESIGN NOTE:
  CPU pins for signals USB1_PWR_EN, USB0_ID has been moved to another pad, software change will be required.
- Hardware design courses
- http://www.fedevel.com/academy/
- CONFIDENTAL. Do not distribute.
- Variant:
- Checked by

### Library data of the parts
C79 C81 C82 = C1005X5R1E224M: as C3 on sheet [04] - CPU - DDR3, DDR3 MEM
C80 = C1608X5R0J106M: as C19 on sheet [04] - CPU - DDR3, DDR3 MEM
R35 = RC0402FR-0722RL: RES 22.0 OHM 1/16W 1% 0402 SMD; Manufacturer: Yageo; Resistance (Ohms): 22; Power (Watts): 0.063W, 1/16W; .Checked PCB: used; Temperature Coefficient: ±100ppm/°C
R88 = RC0402JR-070RL: as R13 on sheet [05] - CPU - PCIE, SATA
R100 = RC0402FR-0710KL: as R6 on sheet [04] - CPU - DDR3, DDR3 MEM
U1 = MCIMX6Q5EYM10AC: as U1 on sheet [04] - CPU - DDR3, DDR3 MEM

## Sheet [09] - CPU - UART, AUDIO.SchDoc
size A2; DocumentNumber: 9; SheetNumber: 9; SheetTotal: 20
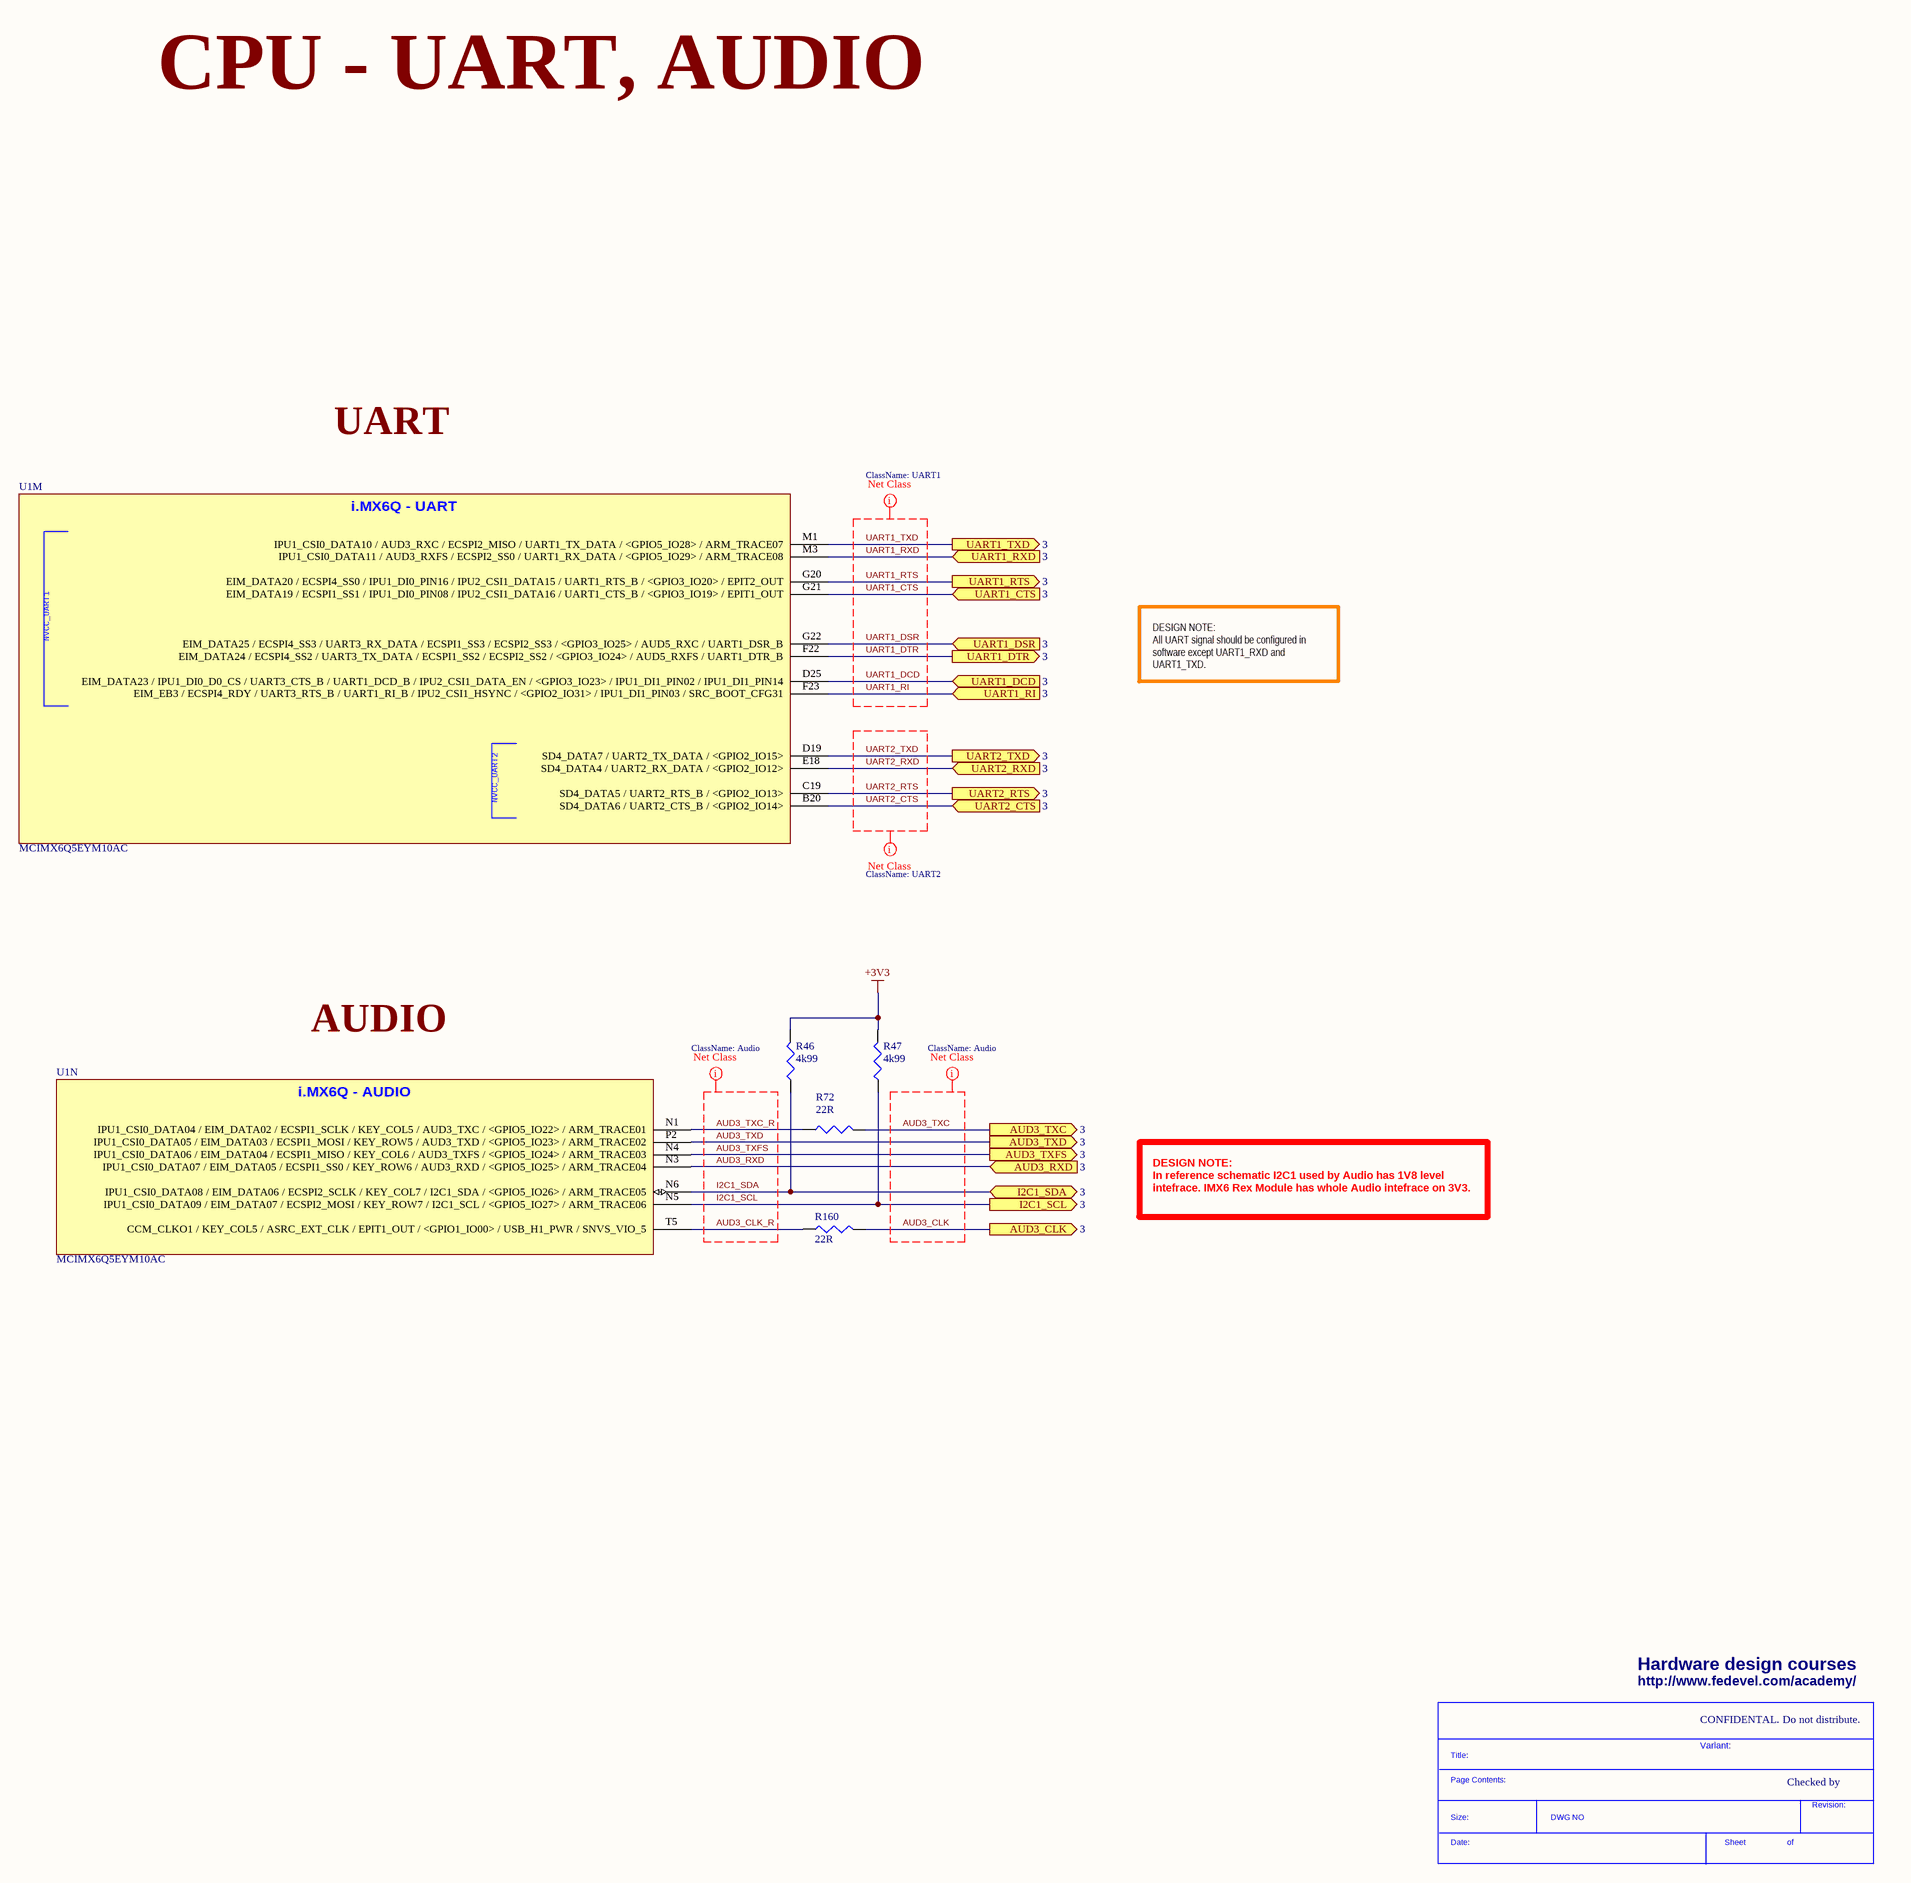
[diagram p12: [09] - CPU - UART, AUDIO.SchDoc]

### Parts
(Parts that share a designator on the sheet are numbered #1, #2 ... from top to bottom, then left to right.)
*#9  SDTitleBlock  (value not drawn)  (graphical)
R46  4k99  [R0402]
R47  4k99  [R0402]
R72  22R  [R0402]
R160  22R  [R0402]
U1  MCIMX6Q5EYM10AC  [PBGA624]  (parts M,N of 15)

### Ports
AUD3_CLK (out, see 3), AUD3_RXD (in, see 3), AUD3_TXC (out, see 3), AUD3_TXD (out, see 3), AUD3_TXFS (out, see 3), I2C1_SCL (out, see 3), I2C1_SDA (bidir, see 3), UART1_CTS (in, see 3), UART1_DCD (in, see 3), UART1_DSR (in, see 3), UART1_DTR (out, see 3), UART1_RI (in, see 3), UART1_RTS (out, see 3), UART1_RXD (in, see 3), UART1_TXD (out, see 3), UART2_CTS (in, see 3), UART2_RTS (out, see 3), UART2_RXD (in, see 3), UART2_TXD (out, see 3)

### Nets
+3V3: R46.2 R47.2
AUD3_CLK: R160.2 ; port AUD3_CLK
AUD3_CLK_R: R160.1 U1.T5(CCM_CLKO1_/_KEY_COL5_/_ASRC_EXT_CLK_/_EPIT1_OUT_/_<GPIO1_IO00>_/_USB_H1_PWR_/_SNVS_VIO_5)
AUD3_RXD: U1.N3(IPU1_CSI0_DATA07_/_EIM_DATA05_/_ECSPI1_SS0_/_KEY_ROW6_/_AUD3_RXD_/_<GPIO5_IO25>_/_ARM_TRACE04) ; port AUD3_RXD
AUD3_TXC: R72.2 ; port AUD3_TXC
AUD3_TXC_R: R72.1 U1.N1(IPU1_CSI0_DATA04_/_EIM_DATA02_/_ECSPI1_SCLK_/_KEY_COL5_/_AUD3_TXC_/_<GPIO5_IO22>_/_ARM_TRACE01)
AUD3_TXD: U1.P2(IPU1_CSI0_DATA05_/_EIM_DATA03_/_ECSPI1_MOSI_/_KEY_ROW5_/_AUD3_TXD_/_<GPIO5_IO23>_/_ARM_TRACE02) ; port AUD3_TXD
AUD3_TXFS: U1.N4(IPU1_CSI0_DATA06_/_EIM_DATA04_/_ECSPI1_MISO_/_KEY_COL6_/_AUD3_TXFS_/_<GPIO5_IO24>_/_ARM_TRACE03) ; port AUD3_TXFS
I2C1_SCL: R47.1 U1.N5(IPU1_CSI0_DATA09_/_EIM_DATA07_/_ECSPI2_MOSI_/_KEY_ROW7_/_I2C1_SCL_/_<GPIO5_IO27>_/_ARM_TRACE06) ; port I2C1_SCL
I2C1_SDA: R46.1 U1.N6(IPU1_CSI0_DATA08_/_EIM_DATA06_/_ECSPI2_SCLK_/_KEY_COL7_/_I2C1_SDA_/_<GPIO5_IO26>_/_ARM_TRACE05) ; port I2C1_SDA
UART1_CTS: U1.G21(EIM_DATA19_/_ECSPI1_SS1_/_IPU1_DI0_PIN08_/_IPU2_CSI1_DATA16_/_UART1_CTS_B_/_<GPIO3_IO19>_/_EPIT1_OUT) ; port UART1_CTS
UART1_DCD: U1.D25(EIM_DATA23_/_IPU1_DI0_D0_CS_/_UART3_CTS_B_/_UART1_DCD_B_/_IPU2_CSI1_DATA_EN_/_<GPIO3_IO23>_/_IPU1_DI1_PIN02_/_IPU1_DI1_PIN14) ; port UART1_DCD
UART1_DSR: U1.G22(EIM_DATA25_/_ECSPI4_SS3_/_UART3_RX_DATA_/_ECSPI1_SS3_/_ECSPI2_SS3_/_<GPIO3_IO25>_/_AUD5_RXC_/_UART1_DSR_B) ; port UART1_DSR
UART1_DTR: U1.F22(EIM_DATA24_/_ECSPI4_SS2_/_UART3_TX_DATA_/_ECSPI1_SS2_/_ECSPI2_SS2_/_<GPIO3_IO24>_/_AUD5_RXFS_/_UART1_DTR_B) ; port UART1_DTR
UART1_RI: U1.F23(EIM_EB3_/_ECSPI4_RDY_/_UART3_RTS_B_/_UART1_RI_B_/_IPU2_CSI1_HSYNC_/_<GPIO2_IO31>_/_IPU1_DI1_PIN03_/_SRC_BOOT_CFG31) ; port UART1_RI
UART1_RTS: U1.G20(EIM_DATA20_/_ECSPI4_SS0_/_IPU1_DI0_PIN16_/_IPU2_CSI1_DATA15_/_UART1_RTS_B_/_<GPIO3_IO20>_/_EPIT2_OUT) ; port UART1_RTS
UART1_RXD: U1.M3(IPU1_CSI0_DATA11_/_AUD3_RXFS_/_ECSPI2_SS0_/_UART1_RX_DATA_/_<GPIO5_IO29>_/_ARM_TRACE08) ; port UART1_RXD
UART1_TXD: U1.M1(IPU1_CSI0_DATA10_/_AUD3_RXC_/_ECSPI2_MISO_/_UART1_TX_DATA_/_<GPIO5_IO28>_/_ARM_TRACE07) ; port UART1_TXD
UART2_CTS: U1.B20(SD4_DATA6_/_UART2_CTS_B_/_<GPIO2_IO14>) ; port UART2_CTS
UART2_RTS: U1.C19(SD4_DATA5_/_UART2_RTS_B_/_<GPIO2_IO13>) ; port UART2_RTS
UART2_RXD: U1.E18(SD4_DATA4_/_UART2_RX_DATA_/_<GPIO2_IO12>) ; port UART2_RXD
UART2_TXD: U1.D19(SD4_DATA7_/_UART2_TX_DATA_/_<GPIO2_IO15>) ; port UART2_TXD

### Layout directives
net class UART1: UART1_CTS, UART1_DCD, UART1_DSR, UART1_DTR, UART1_RI, UART1_RTS, UART1_RXD, UART1_TXD
net class UART2: UART2_CTS, UART2_RTS, UART2_RXD, UART2_TXD
net class Audio: AUD3_CLK, AUD3_CLK_R, AUD3_RXD, AUD3_TXC, AUD3_TXC_R, AUD3_TXD, AUD3_TXFS, I2C1_SCL, I2C1_SDA

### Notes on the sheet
- CPU - UART, AUDIO
- UART
- DESIGN NOTE:
  All UART signal should be configured in software except UART1_RXD and UART1_TXD.
- AUDIO
- DESIGN NOTE:
  In reference schematic I2C1 used by Audio has 1V8 level intefrace. IMX6 Rex Module has whole Audio intefrace on 3V3.
- Hardware design courses
- http://www.fedevel.com/academy/
- CONFIDENTAL. Do not distribute.
- Variant:
- Checked by

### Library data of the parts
R46 R47 = RMCF0402FT4K99: as R28 on sheet [06] - CPU - HDMI, LVDS
R72 R160 = RC0402FR-0722RL: as R35 on sheet [07] - CPU - USB, ETHERNET
U1 = MCIMX6Q5EYM10AC: as U1 on sheet [04] - CPU - DDR3, DDR3 MEM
